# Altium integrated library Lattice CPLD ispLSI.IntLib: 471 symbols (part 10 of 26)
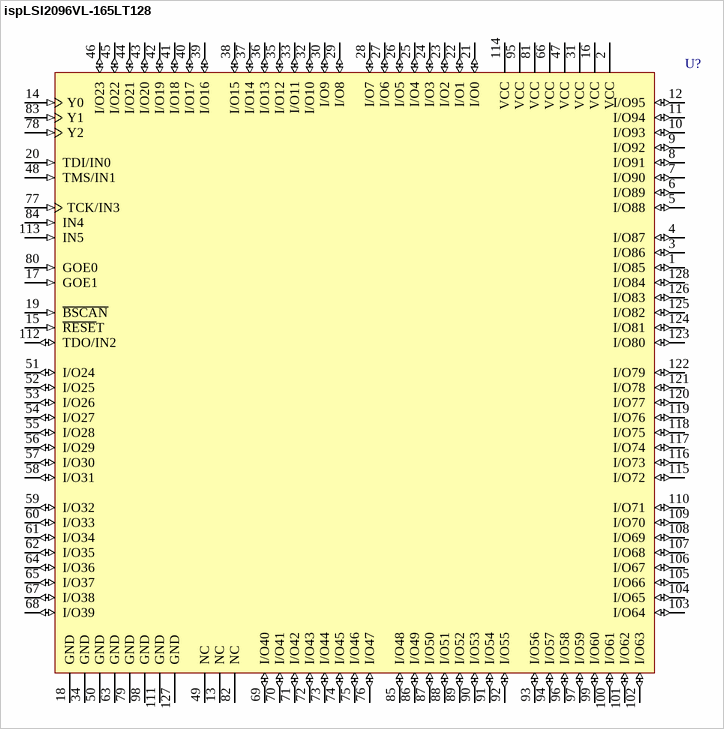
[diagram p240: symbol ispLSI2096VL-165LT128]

## ispLSI2096VL-165LT128
designator U?
2.5V In-System Programmable SuperFAST High Density PLD
footprint TQFP128_N (Thin QFP, 128-Leads, Body 14x14mm, Pitch 0.4mm, IPC Medium Density)
footprint TQFP128_L (Thin QFP, 128-Leads, Body 14x14mm, Pitch 0.4mm, IPC High Density)
footprint TQFP128_M (Thin QFP, 128-Leads, Body 14x14mm, Pitch 0.4mm, IPC Low Density)
3D model 2096VL-TQFP128 (128-Pin Thin Quad Flat Pack 0.4 mm Pitch)
pins: 1 I/O85 (io), 2 VCC (power), 3 I/O86 (io), 4 I/O87 (io), 5 I/O88 (io), 6 I/O89 (io), 7 I/O90 (io), 8 I/O91 (io), 9 I/O92 (io), 10 I/O93 (io), 11 I/O94 (io), 12 I/O95 (io), 13 NC, 14 Y0 (in), 15 ~{RESE}T (in), 16 VCC (power), 17 GOE1 (in), 18 GND (power), 19 ~{BSCAN} (in), 20 TDI/IN0 (in), 21 I/O0 (io), 22 I/O1 (io), 23 I/O2 (io), 24 I/O3 (io), 25 I/O4 (io), 26 I/O5 (io), 27 I/O6 (io), 28 I/O7 (io), 29 I/O8 (io), 30 I/O9 (io), 31 VCC (power), 32 I/O10 (io), 33 I/O11 (io), 34 GND (power), 35 I/O12 (io), 36 I/O13 (io), 37 I/O14 (io), 38 I/O15 (io), 39 I/O16 (io), 40 I/O17 (io), 41 I/O18 (io), 42 I/O19 (io), 43 I/O20 (io), 44 I/O21 (io), 45 I/O22 (io), 46 I/O23 (io), 47 VCC (power), 48 TMS/IN1 (in), 49 NC, 50 GND (power), 51 I/O24 (io), 52 I/O25 (io), 53 I/O26 (io), 54 I/O27 (io), 55 I/O28 (io), 56 I/O29 (io), 57 I/O30 (io), 58 I/O31 (io), 59 I/O32 (io), 60 I/O33 (io), 61 I/O34 (io), 62 I/O35 (io), 63 GND (power), 64 I/O36 (io), 65 I/O37 (io), 66 VCC (power), 67 I/O38 (io), 68 I/O39 (io), 69 I/O40 (io), 70 I/O41 (io), 71 I/O42 (io), 72 I/O43 (io), 73 I/O44 (io), 74 I/O45 (io), 75 I/O46 (io), 76 I/O47 (io), 77 TCK/IN3 (in), 78 Y2 (in), 79 GND (power), 80 GOE0 (in), 81 VCC (power), 82 NC, 83 Y1 (in), 84 IN4 (in), 85 I/O48 (io), 86 I/O49 (io), 87 I/O50 (io), 88 I/O51 (io), 89 I/O52 (io), 90 I/O53 (io), 91 I/O54 (io), 92 I/O55 (io), 93 I/O56 (io), 94 I/O57 (io), 95 VCC (power), 96 I/O58 (io), 97 I/O59 (io), 98 GND (power), 99 I/O60 (io), 100 I/O61 (io), 101 I/O62 (io), 102 I/O63 (io), 103 I/O64 (io), 104 I/O65 (io), 105 I/O66 (io), 106 I/O67 (io), 107 I/O68 (io), 108 I/O69 (io), 109 I/O70 (io), 110 I/O71 (io), 111 GND (power), 112 TDO/IN2 (io), 113 IN5 (in), 114 VCC (power), 115 I/O72 (io), 116 I/O73 (io), 117 I/O74 (io), 118 I/O75 (io), 119 I/O76 (io), 120 I/O77 (io), 121 I/O78 (io), 122 I/O79 (io), 123 I/O80 (io), 124 I/O81 (io), 125 I/O82 (io), 126 I/O83 (io), 127 GND (power), 128 I/O84 (io)

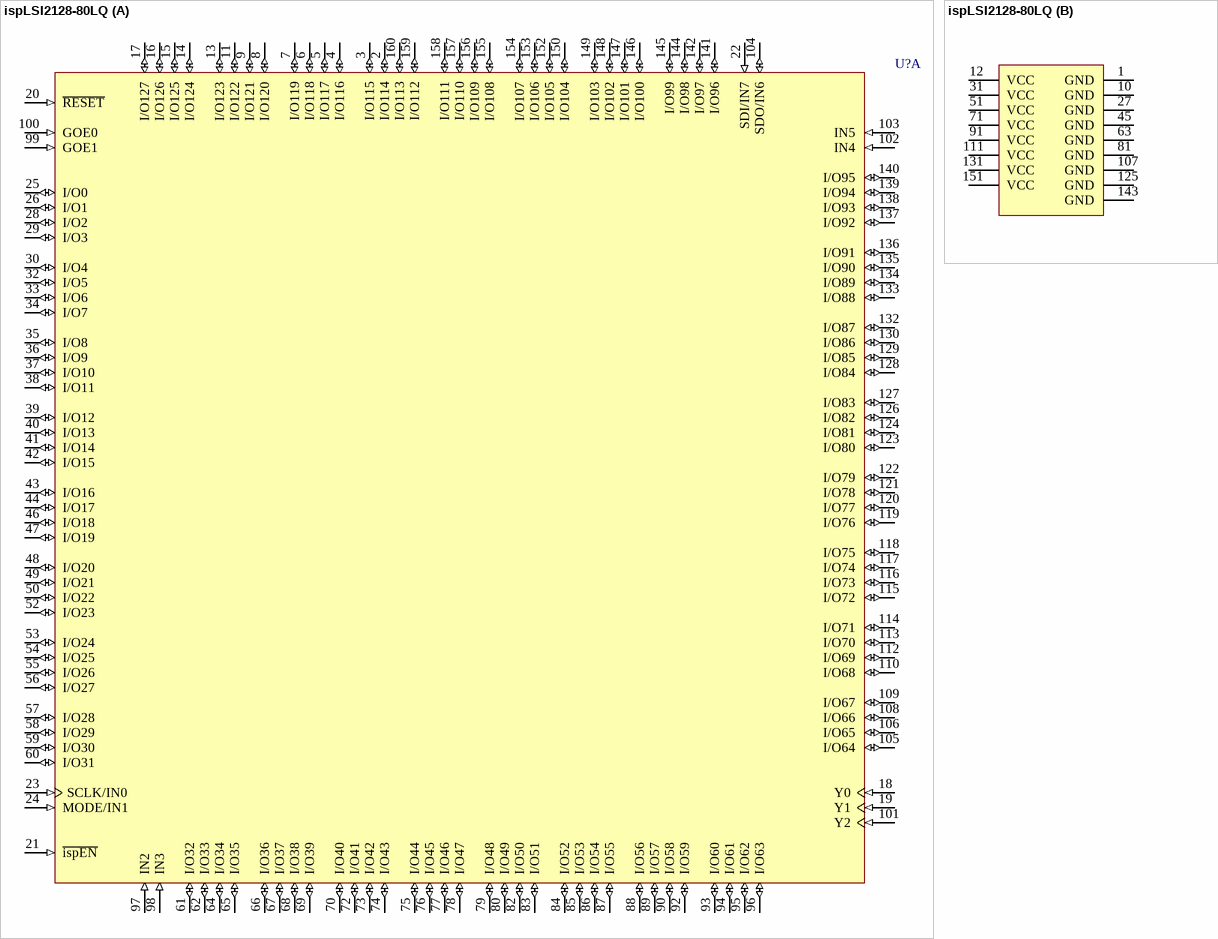
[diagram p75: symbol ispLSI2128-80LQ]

## ispLSI2128-80LQ
designator U?
In-System Programmable High-Density PLD; Note: Pins 22, 23, 24 and 104 have dual function capability.
footprint PQFP160_N (QFP, 160-Leads, Body 28 x 28mm, Pitch 0.65mm, IPC Medium Density)
footprint PQFP160_L (QFP, 160-Leads, Body 28 x 28mm, Pitch 0.65mm, IPC High Density)
footprint PQFP160_M (QFP, 160-Leads, Body 28 x 28mm, Pitch 0.65mm, IPC Low Density)
3D model 2128-PQFP160 (160-Pin Quad Flat Pack 0.65 mm Pitch)
part A pins: 2 I/O114 (io), 3 I/O115 (io), 4 I/O116 (io), 5 I/O117 (io), 6 I/O118 (io), 7 I/O119 (io), 8 I/O120 (io), 9 I/O121 (io), 11 I/O122 (io), 13 I/O123 (io), 14 I/O124 (io), 15 I/O125 (io), 16 I/O126 (io), 17 I/O127 (io), 18 Y0 (in), 19 Y1 (in), 20 ~{RESET} (in), 21 ~{ispEN} (in), 22 SDI/IN7 (in), 23 SCLK/IN0 (in), 24 MODE/IN1 (in), 25 I/O0 (io), 26 I/O1 (io), 28 I/O2 (io), 29 I/O3 (io), 30 I/O4 (io), 32 I/O5 (io), 33 I/O6 (io), 34 I/O7 (io), 35 I/O8 (io), 36 I/O9 (io), 37 I/O10 (io), 38 I/O11 (io), 39 I/O12 (io), 40 I/O13 (io), 41 I/O14 (io), 42 I/O15 (io), 43 I/O16 (io), 44 I/O17 (io), 46 I/O18 (io), 47 I/O19 (io), 48 I/O20 (io), 49 I/O21 (io), 50 I/O22 (io), 52 I/O23 (io), 53 I/O24 (io), 54 I/O25 (io), 55 I/O26 (io), 56 I/O27 (io), 57 I/O28 (io), 58 I/O29 (io), 59 I/O30 (io), 60 I/O31 (io), 61 I/O32 (io), 62 I/O33 (io), 64 I/O34 (io), 65 I/O35 (io), 66 I/O36 (io), 67 I/O37 (io), 68 I/O38 (io), 69 I/O39 (io), 70 I/O40 (io), 72 I/O41 (io), 73 I/O42 (io), 74 I/O43 (io), 75 I/O44 (io), 76 I/O45 (io), 77 I/O46 (io), 78 I/O47 (io), 79 I/O48 (io), 80 I/O49 (io), 82 I/O50 (io), 83 I/O51 (io), 84 I/O52 (io), 85 I/O53 (io), 86 I/O54 (io), 87 I/O55 (io), 88 I/O56 (io), 89 I/O57 (io), 90 I/O58 (io), 92 I/O59 (io), 93 I/O60 (io), 94 I/O61 (io), 95 I/O62 (io), 96 I/O63 (io), 97 IN2 (in), 98 IN3 (in), 99 GOE1 (in), 100 GOE0 (in), 101 Y2 (in), 102 IN4 (in), 103 IN5 (in), 104 SDO/IN6 (io), 105 I/O64 (io), 106 I/O65 (io), 108 I/O66 (io), 109 I/O67 (io), 110 I/O68 (io), 112 I/O69 (io), 113 I/O70 (io), 114 I/O71 (io), 115 I/O72 (io), 116 I/O73 (io), 117 I/O74 (io), 118 I/O75 (io), 119 I/O76 (io), 120 I/O77 (io), 121 I/O78 (io), 122 I/O79 (io), 123 I/O80 (io), 124 I/O81 (io), 126 I/O82 (io), 127 I/O83 (io), 128 I/O84 (io), 129 I/O85 (io), 130 I/O86 (io), 132 I/O87 (io), 133 I/O88 (io), 134 I/O89 (io), 135 I/O90 (io), 136 I/O91 (io), 137 I/O92 (io), 138 I/O93 (io), 139 I/O94 (io), 140 I/O95 (io), 141 I/O96 (io), 142 I/O97 (io), 144 I/O98 (io), 145 I/O99 (io), 146 I/O100 (io), 147 I/O101 (io), 148 I/O102 (io), 149 I/O103 (io), 150 I/O104 (io), 152 I/O105 (io), 153 I/O106 (io), 154 I/O107 (io), 155 I/O108 (io), 156 I/O109 (io), 157 I/O110 (io), 158 I/O111 (io), 159 I/O112 (io), 160 I/O113 (io)
part B pins: 1 GND (power), 10 GND (power), 12 VCC (power), 27 GND (power), 31 VCC (power), 45 GND (power), 51 VCC (power), 63 GND (power), 71 VCC (power), 81 GND (power), 91 VCC (power), 107 GND (power), 111 VCC (power), 125 GND (power), 131 VCC (power), 143 GND (power), 151 VCC (power)

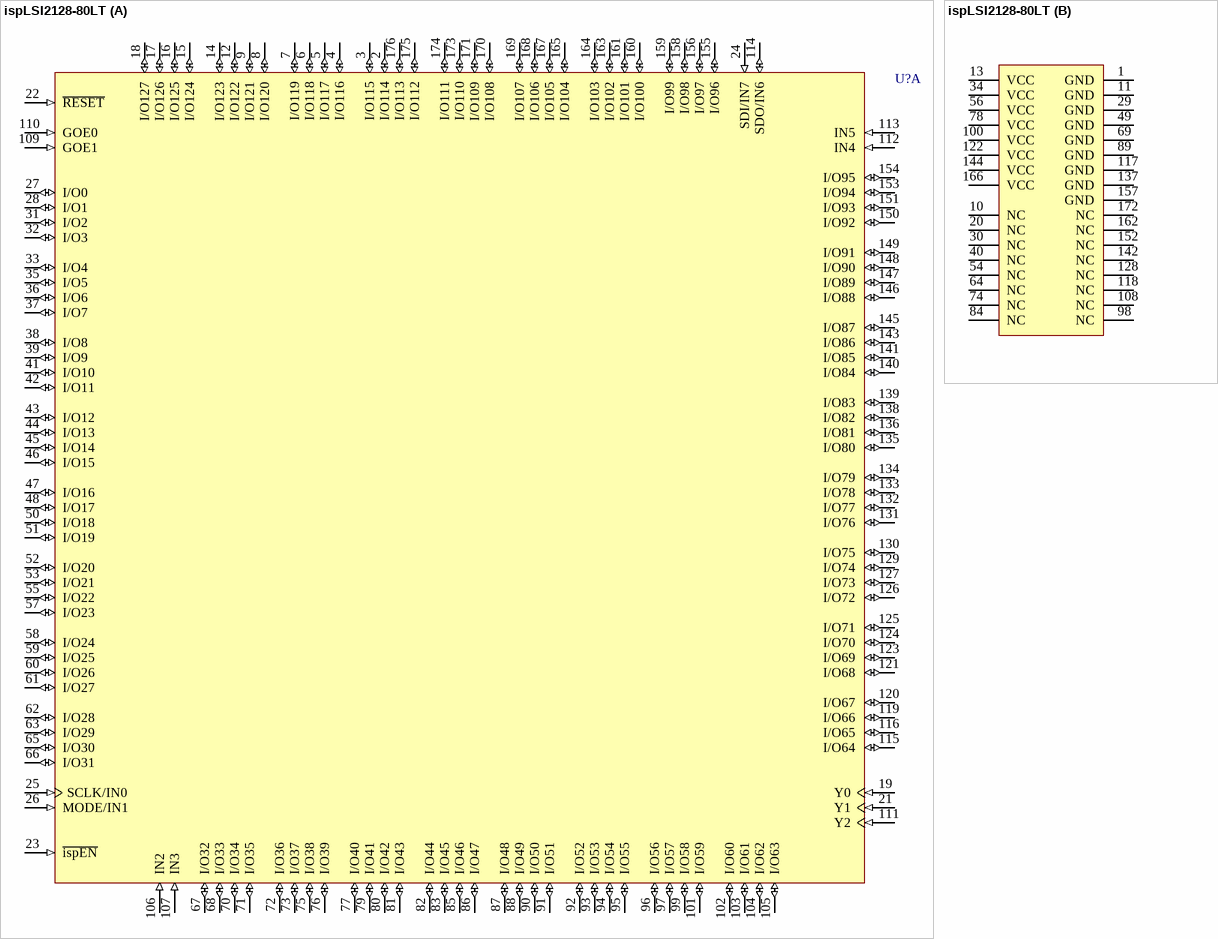
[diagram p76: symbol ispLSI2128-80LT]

## ispLSI2128-80LT
designator U?
In-System Programmable High-Density PLD; Note: Pins 24, 25, 26 and 114 have dual function capability.
footprint TQFP176_N (Thin QFP, 176-Leads, Body 24x24mm, Pitch 0.5mm, IPC Medium Density)
footprint TQFP176_L (Thin QFP, 176-Leads, Body 24x24mm, Pitch 0.5mm, IPC High Density)
footprint TQFP176_M (Thin QFP, 176-Leads, Body 24x24mm, Pitch 0.5mm, IPC Low Density)
3D model 2128-TQFP176 (176-Pin Thin Quad Flat Pack 0.5 mm Pitch)
part A pins: 2 I/O114 (io), 3 I/O115 (io), 4 I/O116 (io), 5 I/O117 (io), 6 I/O118 (io), 7 I/O119 (io), 8 I/O120 (io), 9 I/O121 (io), 12 I/O122 (io), 14 I/O123 (io), 15 I/O124 (io), 16 I/O125 (io), 17 I/O126 (io), 18 I/O127 (io), 19 Y0 (in), 21 Y1 (in), 22 ~{RESET} (in), 23 ~{ispEN} (in), 24 SDI/IN7 (in), 25 SCLK/IN0 (in), 26 MODE/IN1 (in), 27 I/O0 (io), 28 I/O1 (io), 31 I/O2 (io), 32 I/O3 (io), 33 I/O4 (io), 35 I/O5 (io), 36 I/O6 (io), 37 I/O7 (io), 38 I/O8 (io), 39 I/O9 (io), 41 I/O10 (io), 42 I/O11 (io), 43 I/O12 (io), 44 I/O13 (io), 45 I/O14 (io), 46 I/O15 (io), 47 I/O16 (io), 48 I/O17 (io), 50 I/O18 (io), 51 I/O19 (io), 52 I/O20 (io), 53 I/O21 (io), 55 I/O22 (io), 57 I/O23 (io), 58 I/O24 (io), 59 I/O25 (io), 60 I/O26 (io), 61 I/O27 (io), 62 I/O28 (io), 63 I/O29 (io), 65 I/O30 (io), 66 I/O31 (io), 67 I/O32 (io), 68 I/O33 (io), 70 I/O34 (io), 71 I/O35 (io), 72 I/O36 (io), 73 I/O37 (io), 75 I/O38 (io), 76 I/O39 (io), 77 I/O40 (io), 79 I/O41 (io), 80 I/O42 (io), 81 I/O43 (io), 82 I/O44 (io), 83 I/O45 (io), 85 I/O46 (io), 86 I/O47 (io), 87 I/O48 (io), 88 I/O49 (io), 90 I/O50 (io), 91 I/O51 (io), 92 I/O52 (io), 93 I/O53 (io), 94 I/O54 (io), 95 I/O55 (io), 96 I/O56 (io), 97 I/O57 (io), 99 I/O58 (io), 101 I/O59 (io), 102 I/O60 (io), 103 I/O61 (io), 104 I/O62 (io), 105 I/O63 (io), 106 IN2 (in), 107 IN3 (in), 109 GOE1 (in), 110 GOE0 (in), 111 Y2 (in), 112 IN4 (in), 113 IN5 (in), 114 SDO/IN6 (io), 115 I/O64 (io), 116 I/O65 (io), 119 I/O66 (io), 120 I/O67 (io), 121 I/O68 (io), 123 I/O69 (io), 124 I/O70 (io), 125 I/O71 (io), 126 I/O72 (io), 127 I/O73 (io), 129 I/O74 (io), 130 I/O75 (io), 131 I/O76 (io), 132 I/O77 (io), 133 I/O78 (io), 134 I/O79 (io), 135 I/O80 (io), 136 I/O81 (io), 138 I/O82 (io), 139 I/O83 (io), 140 I/O84 (io), 141 I/O85 (io), 143 I/O86 (io), 145 I/O87 (io), 146 I/O88 (io), 147 I/O89 (io), 148 I/O90 (io), 149 I/O91 (io), 150 I/O92 (io), 151 I/O93 (io), 153 I/O94 (io), 154 I/O95 (io), 155 I/O96 (io), 156 I/O97 (io), 158 I/O98 (io), 159 I/O99 (io), 160 I/O100 (io), 161 I/O101 (io), 163 I/O102 (io), 164 I/O103 (io), 165 I/O104 (io), 167 I/O105 (io), 168 I/O106 (io), 169 I/O107 (io), 170 I/O108 (io), 171 I/O109 (io), 173 I/O110 (io), 174 I/O111 (io), 175 I/O112 (io), 176 I/O113 (io)
part B pins: 1 GND (power), 10 NC, 11 GND (power), 13 VCC (power), 20 NC, 29 GND (power), 30 NC, 34 VCC (power), 40 NC, 49 GND (power), 54 NC, 56 VCC (power), 64 NC, 69 GND (power), 74 NC, 78 VCC (power), 84 NC, 89 GND (power), 98 NC, 100 VCC (power), 108 NC, 117 GND (power), 118 NC, 122 VCC (power), 128 NC, 137 GND (power), 142 NC, 144 VCC (power), 152 NC, 157 GND (power), 162 NC, 166 VCC (power), 172 NC

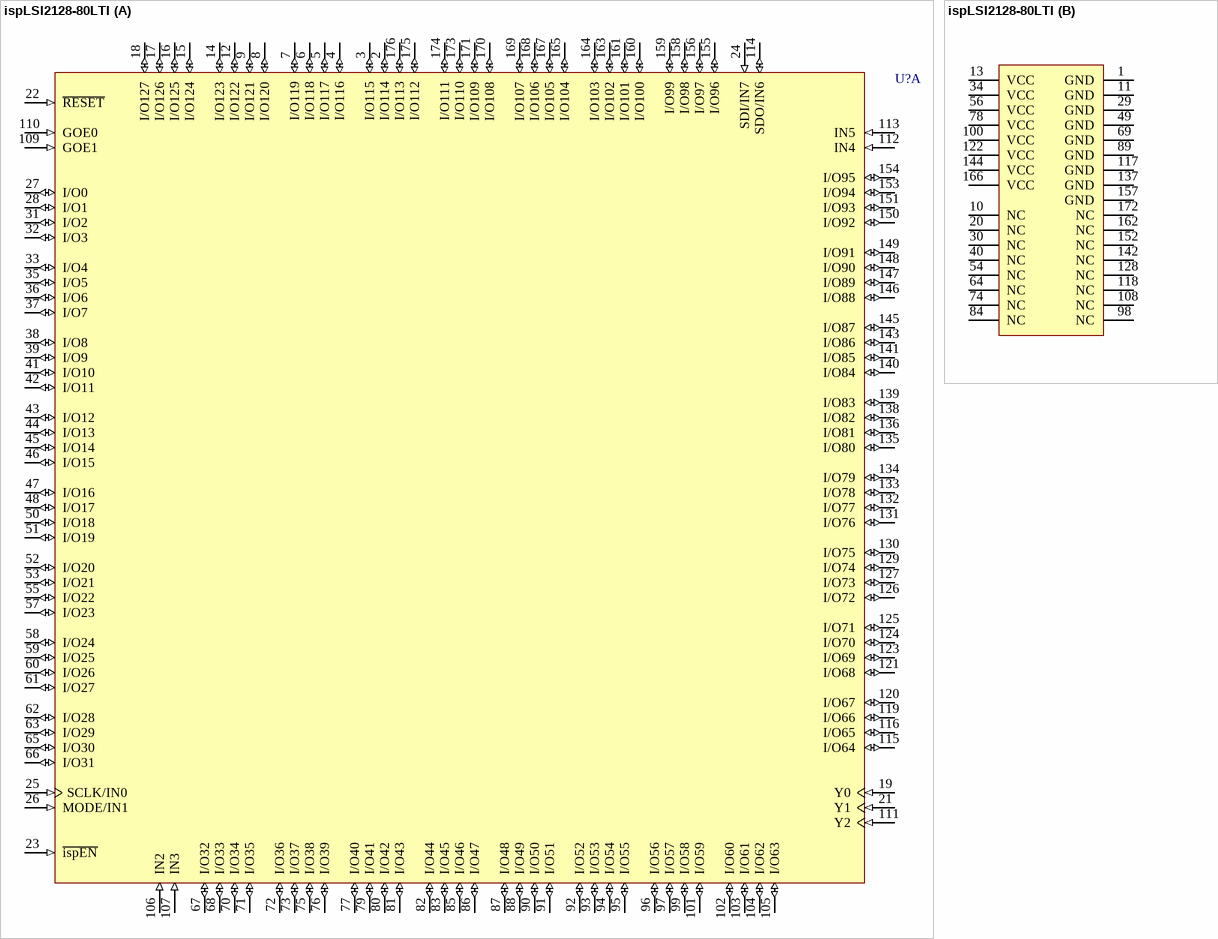
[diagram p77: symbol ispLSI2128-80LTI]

## ispLSI2128-80LTI
designator U?
In-System Programmable High-Density PLD; Note: Pins 24, 25, 26 and 114 have dual function capability.
footprint TQFP176_N (Thin QFP, 176-Leads, Body 24x24mm, Pitch 0.5mm, IPC Medium Density)
footprint TQFP176_L (Thin QFP, 176-Leads, Body 24x24mm, Pitch 0.5mm, IPC High Density)
footprint TQFP176_M (Thin QFP, 176-Leads, Body 24x24mm, Pitch 0.5mm, IPC Low Density)
3D model 2128-TQFP176 (176-Pin Thin Quad Flat Pack 0.5 mm Pitch)
part A pins: 2 I/O114 (io), 3 I/O115 (io), 4 I/O116 (io), 5 I/O117 (io), 6 I/O118 (io), 7 I/O119 (io), 8 I/O120 (io), 9 I/O121 (io), 12 I/O122 (io), 14 I/O123 (io), 15 I/O124 (io), 16 I/O125 (io), 17 I/O126 (io), 18 I/O127 (io), 19 Y0 (in), 21 Y1 (in), 22 ~{RESET} (in), 23 ~{ispEN} (in), 24 SDI/IN7 (in), 25 SCLK/IN0 (in), 26 MODE/IN1 (in), 27 I/O0 (io), 28 I/O1 (io), 31 I/O2 (io), 32 I/O3 (io), 33 I/O4 (io), 35 I/O5 (io), 36 I/O6 (io), 37 I/O7 (io), 38 I/O8 (io), 39 I/O9 (io), 41 I/O10 (io), 42 I/O11 (io), 43 I/O12 (io), 44 I/O13 (io), 45 I/O14 (io), 46 I/O15 (io), 47 I/O16 (io), 48 I/O17 (io), 50 I/O18 (io), 51 I/O19 (io), 52 I/O20 (io), 53 I/O21 (io), 55 I/O22 (io), 57 I/O23 (io), 58 I/O24 (io), 59 I/O25 (io), 60 I/O26 (io), 61 I/O27 (io), 62 I/O28 (io), 63 I/O29 (io), 65 I/O30 (io), 66 I/O31 (io), 67 I/O32 (io), 68 I/O33 (io), 70 I/O34 (io), 71 I/O35 (io), 72 I/O36 (io), 73 I/O37 (io), 75 I/O38 (io), 76 I/O39 (io), 77 I/O40 (io), 79 I/O41 (io), 80 I/O42 (io), 81 I/O43 (io), 82 I/O44 (io), 83 I/O45 (io), 85 I/O46 (io), 86 I/O47 (io), 87 I/O48 (io), 88 I/O49 (io), 90 I/O50 (io), 91 I/O51 (io), 92 I/O52 (io), 93 I/O53 (io), 94 I/O54 (io), 95 I/O55 (io), 96 I/O56 (io), 97 I/O57 (io), 99 I/O58 (io), 101 I/O59 (io), 102 I/O60 (io), 103 I/O61 (io), 104 I/O62 (io), 105 I/O63 (io), 106 IN2 (in), 107 IN3 (in), 109 GOE1 (in), 110 GOE0 (in), 111 Y2 (in), 112 IN4 (in), 113 IN5 (in), 114 SDO/IN6 (io), 115 I/O64 (io), 116 I/O65 (io), 119 I/O66 (io), 120 I/O67 (io), 121 I/O68 (io), 123 I/O69 (io), 124 I/O70 (io), 125 I/O71 (io), 126 I/O72 (io), 127 I/O73 (io), 129 I/O74 (io), 130 I/O75 (io), 131 I/O76 (io), 132 I/O77 (io), 133 I/O78 (io), 134 I/O79 (io), 135 I/O80 (io), 136 I/O81 (io), 138 I/O82 (io), 139 I/O83 (io), 140 I/O84 (io), 141 I/O85 (io), 143 I/O86 (io), 145 I/O87 (io), 146 I/O88 (io), 147 I/O89 (io), 148 I/O90 (io), 149 I/O91 (io), 150 I/O92 (io), 151 I/O93 (io), 153 I/O94 (io), 154 I/O95 (io), 155 I/O96 (io), 156 I/O97 (io), 158 I/O98 (io), 159 I/O99 (io), 160 I/O100 (io), 161 I/O101 (io), 163 I/O102 (io), 164 I/O103 (io), 165 I/O104 (io), 167 I/O105 (io), 168 I/O106 (io), 169 I/O107 (io), 170 I/O108 (io), 171 I/O109 (io), 173 I/O110 (io), 174 I/O111 (io), 175 I/O112 (io), 176 I/O113 (io)
part B pins: 1 GND (power), 10 NC, 11 GND (power), 13 VCC (power), 20 NC, 29 GND (power), 30 NC, 34 VCC (power), 40 NC, 49 GND (power), 54 NC, 56 VCC (power), 64 NC, 69 GND (power), 74 NC, 78 VCC (power), 84 NC, 89 GND (power), 98 NC, 100 VCC (power), 108 NC, 117 GND (power), 118 NC, 122 VCC (power), 128 NC, 137 GND (power), 142 NC, 144 VCC (power), 152 NC, 157 GND (power), 162 NC, 166 VCC (power), 172 NC

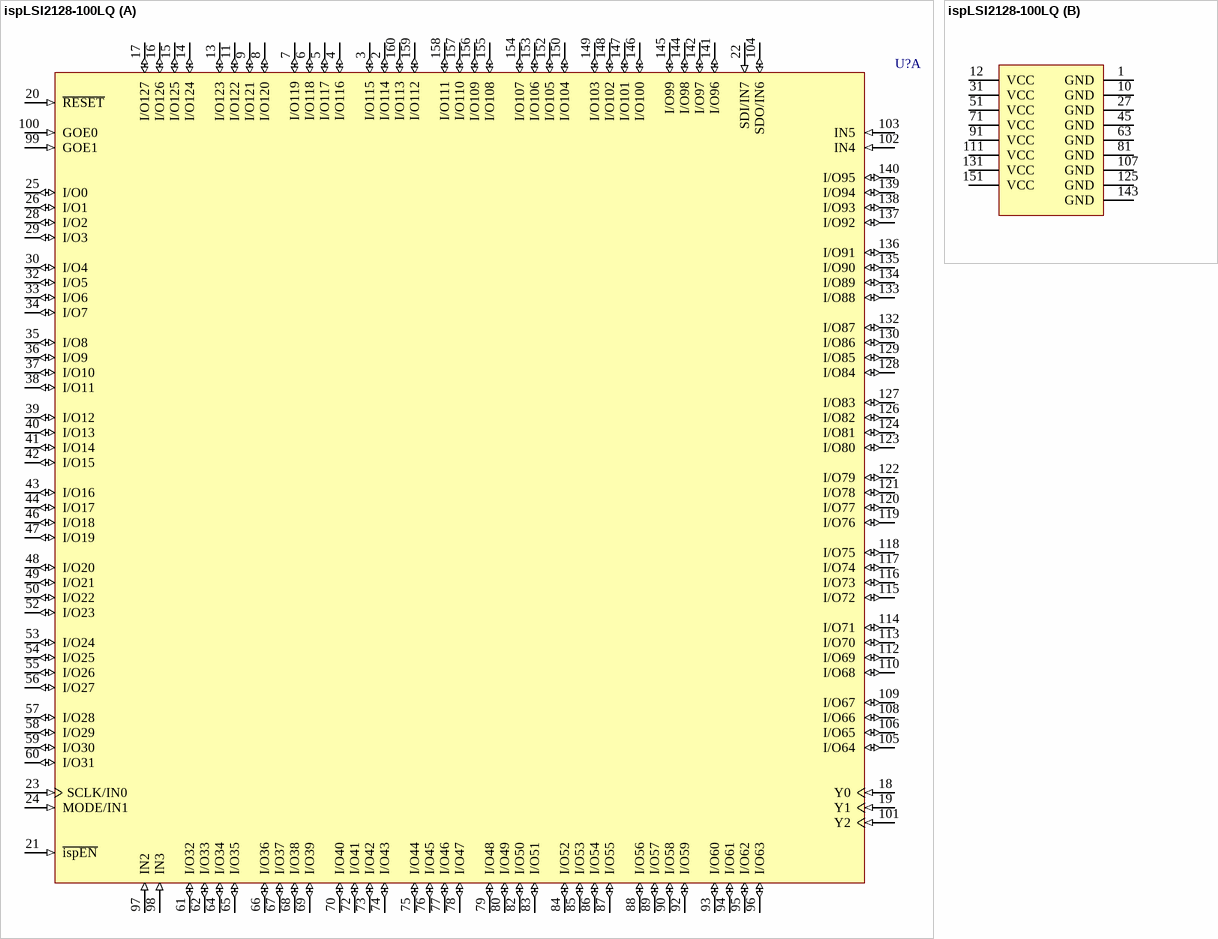
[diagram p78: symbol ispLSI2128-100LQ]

## ispLSI2128-100LQ
designator U?
In-System Programmable High-Density PLD; Note: Pins 22, 23, 24 and 104 have dual function capability.
footprint PQFP160_N (QFP, 160-Leads, Body 28 x 28mm, Pitch 0.65mm, IPC Medium Density)
footprint PQFP160_L (QFP, 160-Leads, Body 28 x 28mm, Pitch 0.65mm, IPC High Density)
footprint PQFP160_M (QFP, 160-Leads, Body 28 x 28mm, Pitch 0.65mm, IPC Low Density)
3D model 2128-PQFP160 (160-Pin Quad Flat Pack 0.65 mm Pitch)
part A pins: 2 I/O114 (io), 3 I/O115 (io), 4 I/O116 (io), 5 I/O117 (io), 6 I/O118 (io), 7 I/O119 (io), 8 I/O120 (io), 9 I/O121 (io), 11 I/O122 (io), 13 I/O123 (io), 14 I/O124 (io), 15 I/O125 (io), 16 I/O126 (io), 17 I/O127 (io), 18 Y0 (in), 19 Y1 (in), 20 ~{RESET} (in), 21 ~{ispEN} (in), 22 SDI/IN7 (in), 23 SCLK/IN0 (in), 24 MODE/IN1 (in), 25 I/O0 (io), 26 I/O1 (io), 28 I/O2 (io), 29 I/O3 (io), 30 I/O4 (io), 32 I/O5 (io), 33 I/O6 (io), 34 I/O7 (io), 35 I/O8 (io), 36 I/O9 (io), 37 I/O10 (io), 38 I/O11 (io), 39 I/O12 (io), 40 I/O13 (io), 41 I/O14 (io), 42 I/O15 (io), 43 I/O16 (io), 44 I/O17 (io), 46 I/O18 (io), 47 I/O19 (io), 48 I/O20 (io), 49 I/O21 (io), 50 I/O22 (io), 52 I/O23 (io), 53 I/O24 (io), 54 I/O25 (io), 55 I/O26 (io), 56 I/O27 (io), 57 I/O28 (io), 58 I/O29 (io), 59 I/O30 (io), 60 I/O31 (io), 61 I/O32 (io), 62 I/O33 (io), 64 I/O34 (io), 65 I/O35 (io), 66 I/O36 (io), 67 I/O37 (io), 68 I/O38 (io), 69 I/O39 (io), 70 I/O40 (io), 72 I/O41 (io), 73 I/O42 (io), 74 I/O43 (io), 75 I/O44 (io), 76 I/O45 (io), 77 I/O46 (io), 78 I/O47 (io), 79 I/O48 (io), 80 I/O49 (io), 82 I/O50 (io), 83 I/O51 (io), 84 I/O52 (io), 85 I/O53 (io), 86 I/O54 (io), 87 I/O55 (io), 88 I/O56 (io), 89 I/O57 (io), 90 I/O58 (io), 92 I/O59 (io), 93 I/O60 (io), 94 I/O61 (io), 95 I/O62 (io), 96 I/O63 (io), 97 IN2 (in), 98 IN3 (in), 99 GOE1 (in), 100 GOE0 (in), 101 Y2 (in), 102 IN4 (in), 103 IN5 (in), 104 SDO/IN6 (io), 105 I/O64 (io), 106 I/O65 (io), 108 I/O66 (io), 109 I/O67 (io), 110 I/O68 (io), 112 I/O69 (io), 113 I/O70 (io), 114 I/O71 (io), 115 I/O72 (io), 116 I/O73 (io), 117 I/O74 (io), 118 I/O75 (io), 119 I/O76 (io), 120 I/O77 (io), 121 I/O78 (io), 122 I/O79 (io), 123 I/O80 (io), 124 I/O81 (io), 126 I/O82 (io), 127 I/O83 (io), 128 I/O84 (io), 129 I/O85 (io), 130 I/O86 (io), 132 I/O87 (io), 133 I/O88 (io), 134 I/O89 (io), 135 I/O90 (io), 136 I/O91 (io), 137 I/O92 (io), 138 I/O93 (io), 139 I/O94 (io), 140 I/O95 (io), 141 I/O96 (io), 142 I/O97 (io), 144 I/O98 (io), 145 I/O99 (io), 146 I/O100 (io), 147 I/O101 (io), 148 I/O102 (io), 149 I/O103 (io), 150 I/O104 (io), 152 I/O105 (io), 153 I/O106 (io), 154 I/O107 (io), 155 I/O108 (io), 156 I/O109 (io), 157 I/O110 (io), 158 I/O111 (io), 159 I/O112 (io), 160 I/O113 (io)
part B pins: 1 GND (power), 10 GND (power), 12 VCC (power), 27 GND (power), 31 VCC (power), 45 GND (power), 51 VCC (power), 63 GND (power), 71 VCC (power), 81 GND (power), 91 VCC (power), 107 GND (power), 111 VCC (power), 125 GND (power), 131 VCC (power), 143 GND (power), 151 VCC (power)

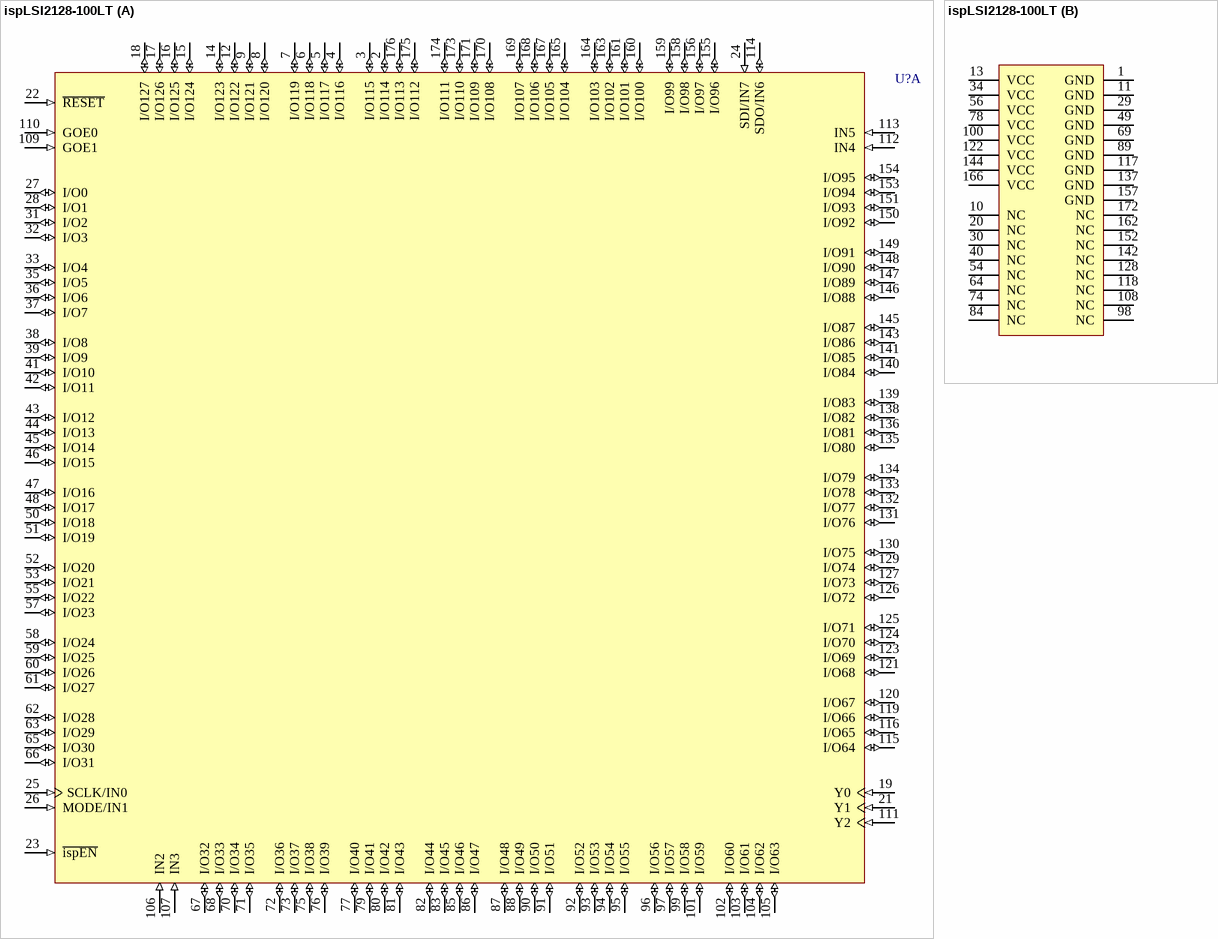
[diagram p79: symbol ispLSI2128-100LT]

## ispLSI2128-100LT
designator U?
In-System Programmable High-Density PLD; Note: Pins 24, 25, 26 and 114 have dual function capability.
footprint TQFP176_N (Thin QFP, 176-Leads, Body 24x24mm, Pitch 0.5mm, IPC Medium Density)
footprint TQFP176_L (Thin QFP, 176-Leads, Body 24x24mm, Pitch 0.5mm, IPC High Density)
footprint TQFP176_M (Thin QFP, 176-Leads, Body 24x24mm, Pitch 0.5mm, IPC Low Density)
3D model 2128-TQFP176 (176-Pin Thin Quad Flat Pack 0.5 mm Pitch)
part A pins: 2 I/O114 (io), 3 I/O115 (io), 4 I/O116 (io), 5 I/O117 (io), 6 I/O118 (io), 7 I/O119 (io), 8 I/O120 (io), 9 I/O121 (io), 12 I/O122 (io), 14 I/O123 (io), 15 I/O124 (io), 16 I/O125 (io), 17 I/O126 (io), 18 I/O127 (io), 19 Y0 (in), 21 Y1 (in), 22 ~{RESET} (in), 23 ~{ispEN} (in), 24 SDI/IN7 (in), 25 SCLK/IN0 (in), 26 MODE/IN1 (in), 27 I/O0 (io), 28 I/O1 (io), 31 I/O2 (io), 32 I/O3 (io), 33 I/O4 (io), 35 I/O5 (io), 36 I/O6 (io), 37 I/O7 (io), 38 I/O8 (io), 39 I/O9 (io), 41 I/O10 (io), 42 I/O11 (io), 43 I/O12 (io), 44 I/O13 (io), 45 I/O14 (io), 46 I/O15 (io), 47 I/O16 (io), 48 I/O17 (io), 50 I/O18 (io), 51 I/O19 (io), 52 I/O20 (io), 53 I/O21 (io), 55 I/O22 (io), 57 I/O23 (io), 58 I/O24 (io), 59 I/O25 (io), 60 I/O26 (io), 61 I/O27 (io), 62 I/O28 (io), 63 I/O29 (io), 65 I/O30 (io), 66 I/O31 (io), 67 I/O32 (io), 68 I/O33 (io), 70 I/O34 (io), 71 I/O35 (io), 72 I/O36 (io), 73 I/O37 (io), 75 I/O38 (io), 76 I/O39 (io), 77 I/O40 (io), 79 I/O41 (io), 80 I/O42 (io), 81 I/O43 (io), 82 I/O44 (io), 83 I/O45 (io), 85 I/O46 (io), 86 I/O47 (io), 87 I/O48 (io), 88 I/O49 (io), 90 I/O50 (io), 91 I/O51 (io), 92 I/O52 (io), 93 I/O53 (io), 94 I/O54 (io), 95 I/O55 (io), 96 I/O56 (io), 97 I/O57 (io), 99 I/O58 (io), 101 I/O59 (io), 102 I/O60 (io), 103 I/O61 (io), 104 I/O62 (io), 105 I/O63 (io), 106 IN2 (in), 107 IN3 (in), 109 GOE1 (in), 110 GOE0 (in), 111 Y2 (in), 112 IN4 (in), 113 IN5 (in), 114 SDO/IN6 (io), 115 I/O64 (io), 116 I/O65 (io), 119 I/O66 (io), 120 I/O67 (io), 121 I/O68 (io), 123 I/O69 (io), 124 I/O70 (io), 125 I/O71 (io), 126 I/O72 (io), 127 I/O73 (io), 129 I/O74 (io), 130 I/O75 (io), 131 I/O76 (io), 132 I/O77 (io), 133 I/O78 (io), 134 I/O79 (io), 135 I/O80 (io), 136 I/O81 (io), 138 I/O82 (io), 139 I/O83 (io), 140 I/O84 (io), 141 I/O85 (io), 143 I/O86 (io), 145 I/O87 (io), 146 I/O88 (io), 147 I/O89 (io), 148 I/O90 (io), 149 I/O91 (io), 150 I/O92 (io), 151 I/O93 (io), 153 I/O94 (io), 154 I/O95 (io), 155 I/O96 (io), 156 I/O97 (io), 158 I/O98 (io), 159 I/O99 (io), 160 I/O100 (io), 161 I/O101 (io), 163 I/O102 (io), 164 I/O103 (io), 165 I/O104 (io), 167 I/O105 (io), 168 I/O106 (io), 169 I/O107 (io), 170 I/O108 (io), 171 I/O109 (io), 173 I/O110 (io), 174 I/O111 (io), 175 I/O112 (io), 176 I/O113 (io)
part B pins: 1 GND (power), 10 NC, 11 GND (power), 13 VCC (power), 20 NC, 29 GND (power), 30 NC, 34 VCC (power), 40 NC, 49 GND (power), 54 NC, 56 VCC (power), 64 NC, 69 GND (power), 74 NC, 78 VCC (power), 84 NC, 89 GND (power), 98 NC, 100 VCC (power), 108 NC, 117 GND (power), 118 NC, 122 VCC (power), 128 NC, 137 GND (power), 142 NC, 144 VCC (power), 152 NC, 157 GND (power), 162 NC, 166 VCC (power), 172 NC

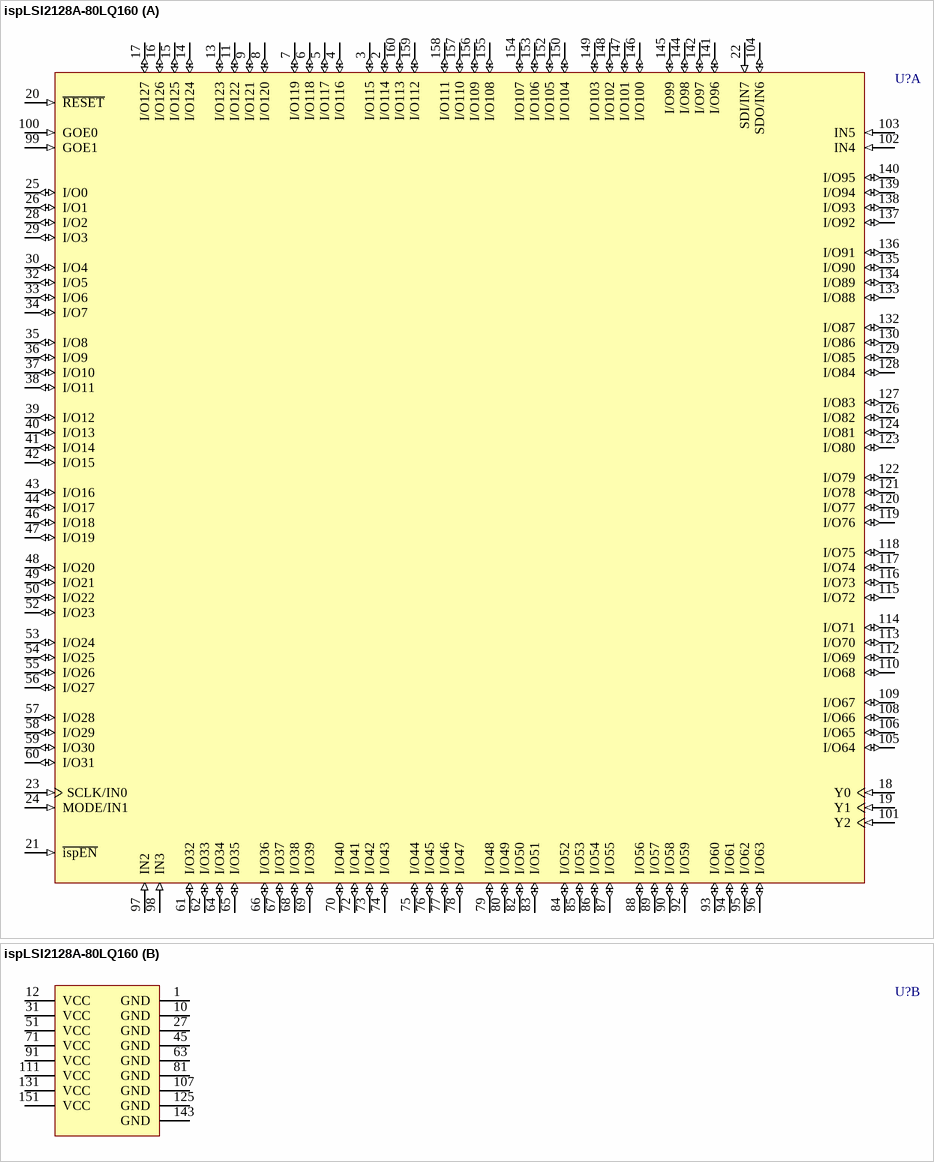
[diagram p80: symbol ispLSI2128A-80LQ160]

## ispLSI2128A-80LQ160
designator U?
In-System Programmable High-Density PLD; Note: Pins 22, 23, 24 and 104 have dual function capability.
footprint PQFP160_N (QFP, 160-Leads, Body 28 x 28mm, Pitch 0.65mm, IPC Medium Density)
footprint PQFP160_L (QFP, 160-Leads, Body 28 x 28mm, Pitch 0.65mm, IPC High Density)
footprint PQFP160_M (QFP, 160-Leads, Body 28 x 28mm, Pitch 0.65mm, IPC Low Density)
3D model 2128A-PQFP160 (160-Pin Quad Flat Pack 0.65 mm Pitch)
part A pins: 2 I/O114 (io), 3 I/O115 (io), 4 I/O116 (io), 5 I/O117 (io), 6 I/O118 (io), 7 I/O119 (io), 8 I/O120 (io), 9 I/O121 (io), 11 I/O122 (io), 13 I/O123 (io), 14 I/O124 (io), 15 I/O125 (io), 16 I/O126 (io), 17 I/O127 (io), 18 Y0 (in), 19 Y1 (in), 20 ~{RESET} (in), 21 ~{ispEN} (in), 22 SDI/IN7 (in), 23 SCLK/IN0 (in), 24 MODE/IN1 (in), 25 I/O0 (io), 26 I/O1 (io), 28 I/O2 (io), 29 I/O3 (io), 30 I/O4 (io), 32 I/O5 (io), 33 I/O6 (io), 34 I/O7 (io), 35 I/O8 (io), 36 I/O9 (io), 37 I/O10 (io), 38 I/O11 (io), 39 I/O12 (io), 40 I/O13 (io), 41 I/O14 (io), 42 I/O15 (io), 43 I/O16 (io), 44 I/O17 (io), 46 I/O18 (io), 47 I/O19 (io), 48 I/O20 (io), 49 I/O21 (io), 50 I/O22 (io), 52 I/O23 (io), 53 I/O24 (io), 54 I/O25 (io), 55 I/O26 (io), 56 I/O27 (io), 57 I/O28 (io), 58 I/O29 (io), 59 I/O30 (io), 60 I/O31 (io), 61 I/O32 (io), 62 I/O33 (io), 64 I/O34 (io), 65 I/O35 (io), 66 I/O36 (io), 67 I/O37 (io), 68 I/O38 (io), 69 I/O39 (io), 70 I/O40 (io), 72 I/O41 (io), 73 I/O42 (io), 74 I/O43 (io), 75 I/O44 (io), 76 I/O45 (io), 77 I/O46 (io), 78 I/O47 (io), 79 I/O48 (io), 80 I/O49 (io), 82 I/O50 (io), 83 I/O51 (io), 84 I/O52 (io), 85 I/O53 (io), 86 I/O54 (io), 87 I/O55 (io), 88 I/O56 (io), 89 I/O57 (io), 90 I/O58 (io), 92 I/O59 (io), 93 I/O60 (io), 94 I/O61 (io), 95 I/O62 (io), 96 I/O63 (io), 97 IN2 (in), 98 IN3 (in), 99 GOE1 (in), 100 GOE0 (in), 101 Y2 (in), 102 IN4 (in), 103 IN5 (in), 104 SDO/IN6 (io), 105 I/O64 (io), 106 I/O65 (io), 108 I/O66 (io), 109 I/O67 (io), 110 I/O68 (io), 112 I/O69 (io), 113 I/O70 (io), 114 I/O71 (io), 115 I/O72 (io), 116 I/O73 (io), 117 I/O74 (io), 118 I/O75 (io), 119 I/O76 (io), 120 I/O77 (io), 121 I/O78 (io), 122 I/O79 (io), 123 I/O80 (io), 124 I/O81 (io), 126 I/O82 (io), 127 I/O83 (io), 128 I/O84 (io), 129 I/O85 (io), 130 I/O86 (io), 132 I/O87 (io), 133 I/O88 (io), 134 I/O89 (io), 135 I/O90 (io), 136 I/O91 (io), 137 I/O92 (io), 138 I/O93 (io), 139 I/O94 (io), 140 I/O95 (io), 141 I/O96 (io), 142 I/O97 (io), 144 I/O98 (io), 145 I/O99 (io), 146 I/O100 (io), 147 I/O101 (io), 148 I/O102 (io), 149 I/O103 (io), 150 I/O104 (io), 152 I/O105 (io), 153 I/O106 (io), 154 I/O107 (io), 155 I/O108 (io), 156 I/O109 (io), 157 I/O110 (io), 158 I/O111 (io), 159 I/O112 (io), 160 I/O113 (io)
part B pins: 1 GND (power), 10 GND (power), 12 VCC (power), 27 GND (power), 31 VCC (power), 45 GND (power), 51 VCC (power), 63 GND (power), 71 VCC (power), 81 GND (power), 91 VCC (power), 107 GND (power), 111 VCC (power), 125 GND (power), 131 VCC (power), 143 GND (power), 151 VCC (power)

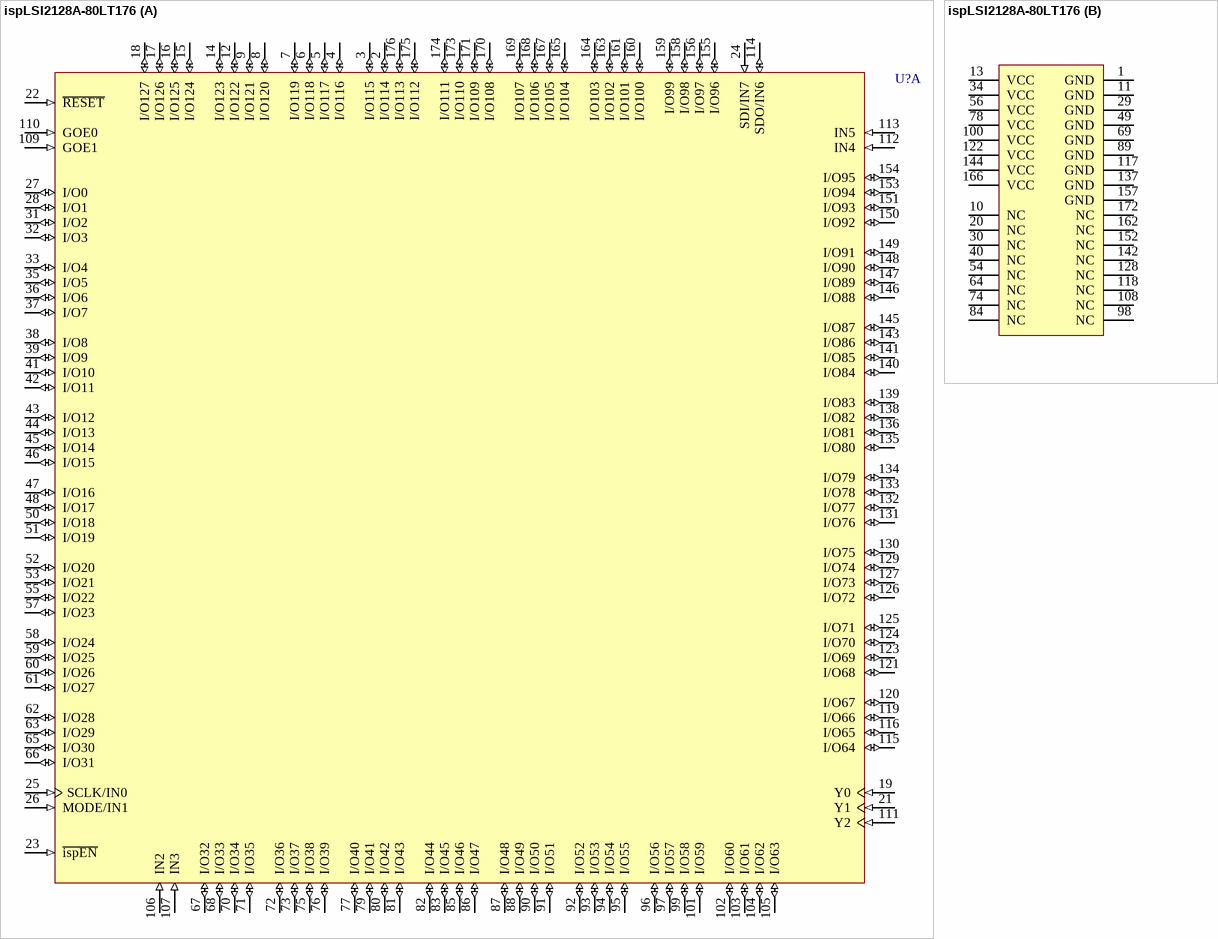
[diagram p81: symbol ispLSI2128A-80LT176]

## ispLSI2128A-80LT176
designator U?
In-System Programmable High-Density PLD; Note: Pins 24, 25, 26 and 114 have dual function capability.
footprint TQFP176_N (Thin QFP, 176-Leads, Body 24x24mm, Pitch 0.5mm, IPC Medium Density)
footprint TQFP176_L (Thin QFP, 176-Leads, Body 24x24mm, Pitch 0.5mm, IPC High Density)
footprint TQFP176_M (Thin QFP, 176-Leads, Body 24x24mm, Pitch 0.5mm, IPC Low Density)
3D model 2128A-TQFP176 (176-Pin Thin Quad Flat Pack 0.5 mm Pitch)
part A pins: 2 I/O114 (io), 3 I/O115 (io), 4 I/O116 (io), 5 I/O117 (io), 6 I/O118 (io), 7 I/O119 (io), 8 I/O120 (io), 9 I/O121 (io), 12 I/O122 (io), 14 I/O123 (io), 15 I/O124 (io), 16 I/O125 (io), 17 I/O126 (io), 18 I/O127 (io), 19 Y0 (in), 21 Y1 (in), 22 ~{RESET} (in), 23 ~{ispEN} (in), 24 SDI/IN7 (in), 25 SCLK/IN0 (in), 26 MODE/IN1 (in), 27 I/O0 (io), 28 I/O1 (io), 31 I/O2 (io), 32 I/O3 (io), 33 I/O4 (io), 35 I/O5 (io), 36 I/O6 (io), 37 I/O7 (io), 38 I/O8 (io), 39 I/O9 (io), 41 I/O10 (io), 42 I/O11 (io), 43 I/O12 (io), 44 I/O13 (io), 45 I/O14 (io), 46 I/O15 (io), 47 I/O16 (io), 48 I/O17 (io), 50 I/O18 (io), 51 I/O19 (io), 52 I/O20 (io), 53 I/O21 (io), 55 I/O22 (io), 57 I/O23 (io), 58 I/O24 (io), 59 I/O25 (io), 60 I/O26 (io), 61 I/O27 (io), 62 I/O28 (io), 63 I/O29 (io), 65 I/O30 (io), 66 I/O31 (io), 67 I/O32 (io), 68 I/O33 (io), 70 I/O34 (io), 71 I/O35 (io), 72 I/O36 (io), 73 I/O37 (io), 75 I/O38 (io), 76 I/O39 (io), 77 I/O40 (io), 79 I/O41 (io), 80 I/O42 (io), 81 I/O43 (io), 82 I/O44 (io), 83 I/O45 (io), 85 I/O46 (io), 86 I/O47 (io), 87 I/O48 (io), 88 I/O49 (io), 90 I/O50 (io), 91 I/O51 (io), 92 I/O52 (io), 93 I/O53 (io), 94 I/O54 (io), 95 I/O55 (io), 96 I/O56 (io), 97 I/O57 (io), 99 I/O58 (io), 101 I/O59 (io), 102 I/O60 (io), 103 I/O61 (io), 104 I/O62 (io), 105 I/O63 (io), 106 IN2 (in), 107 IN3 (in), 109 GOE1 (in), 110 GOE0 (in), 111 Y2 (in), 112 IN4 (in), 113 IN5 (in), 114 SDO/IN6 (io), 115 I/O64 (io), 116 I/O65 (io), 119 I/O66 (io), 120 I/O67 (io), 121 I/O68 (io), 123 I/O69 (io), 124 I/O70 (io), 125 I/O71 (io), 126 I/O72 (io), 127 I/O73 (io), 129 I/O74 (io), 130 I/O75 (io), 131 I/O76 (io), 132 I/O77 (io), 133 I/O78 (io), 134 I/O79 (io), 135 I/O80 (io), 136 I/O81 (io), 138 I/O82 (io), 139 I/O83 (io), 140 I/O84 (io), 141 I/O85 (io), 143 I/O86 (io), 145 I/O87 (io), 146 I/O88 (io), 147 I/O89 (io), 148 I/O90 (io), 149 I/O91 (io), 150 I/O92 (io), 151 I/O93 (io), 153 I/O94 (io), 154 I/O95 (io), 155 I/O96 (io), 156 I/O97 (io), 158 I/O98 (io), 159 I/O99 (io), 160 I/O100 (io), 161 I/O101 (io), 163 I/O102 (io), 164 I/O103 (io), 165 I/O104 (io), 167 I/O105 (io), 168 I/O106 (io), 169 I/O107 (io), 170 I/O108 (io), 171 I/O109 (io), 173 I/O110 (io), 174 I/O111 (io), 175 I/O112 (io), 176 I/O113 (io)
part B pins: 1 GND (power), 10 NC, 11 GND (power), 13 VCC (power), 20 NC, 29 GND (power), 30 NC, 34 VCC (power), 40 NC, 49 GND (power), 54 NC, 56 VCC (power), 64 NC, 69 GND (power), 74 NC, 78 VCC (power), 84 NC, 89 GND (power), 98 NC, 100 VCC (power), 108 NC, 117 GND (power), 118 NC, 122 VCC (power), 128 NC, 137 GND (power), 142 NC, 144 VCC (power), 152 NC, 157 GND (power), 162 NC, 166 VCC (power), 172 NC

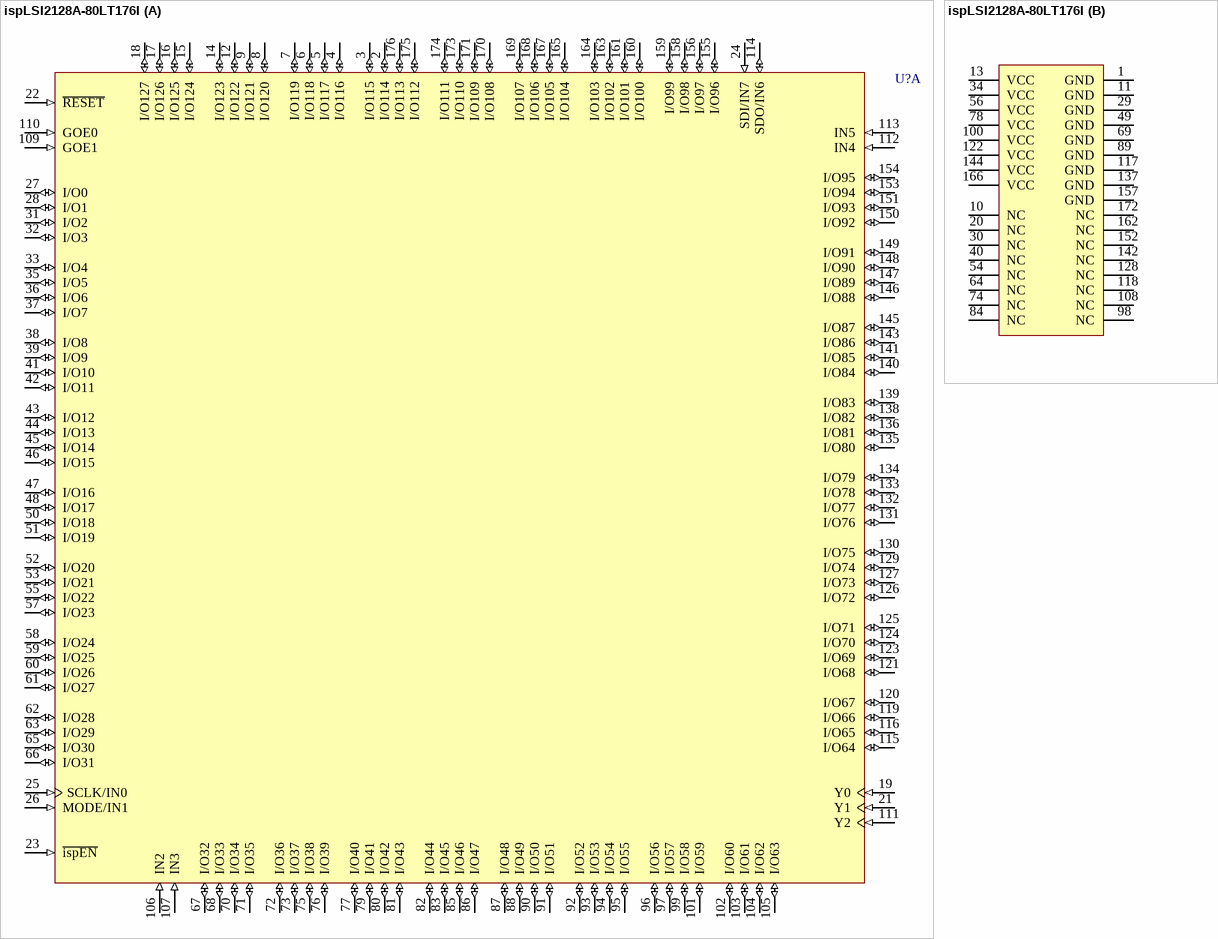
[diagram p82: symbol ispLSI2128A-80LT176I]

## ispLSI2128A-80LT176I
designator U?
In-System Programmable High-Density PLD; Note: Pins 24, 25, 26 and 114 have dual function capability.
footprint TQFP176_N (Thin QFP, 176-Leads, Body 24x24mm, Pitch 0.5mm, IPC Medium Density)
footprint TQFP176_L (Thin QFP, 176-Leads, Body 24x24mm, Pitch 0.5mm, IPC High Density)
footprint TQFP176_M (Thin QFP, 176-Leads, Body 24x24mm, Pitch 0.5mm, IPC Low Density)
3D model 2128A-TQFP176 (176-Pin Thin Quad Flat Pack 0.5 mm Pitch)
part A pins: 2 I/O114 (io), 3 I/O115 (io), 4 I/O116 (io), 5 I/O117 (io), 6 I/O118 (io), 7 I/O119 (io), 8 I/O120 (io), 9 I/O121 (io), 12 I/O122 (io), 14 I/O123 (io), 15 I/O124 (io), 16 I/O125 (io), 17 I/O126 (io), 18 I/O127 (io), 19 Y0 (in), 21 Y1 (in), 22 ~{RESET} (in), 23 ~{ispEN} (in), 24 SDI/IN7 (in), 25 SCLK/IN0 (in), 26 MODE/IN1 (in), 27 I/O0 (io), 28 I/O1 (io), 31 I/O2 (io), 32 I/O3 (io), 33 I/O4 (io), 35 I/O5 (io), 36 I/O6 (io), 37 I/O7 (io), 38 I/O8 (io), 39 I/O9 (io), 41 I/O10 (io), 42 I/O11 (io), 43 I/O12 (io), 44 I/O13 (io), 45 I/O14 (io), 46 I/O15 (io), 47 I/O16 (io), 48 I/O17 (io), 50 I/O18 (io), 51 I/O19 (io), 52 I/O20 (io), 53 I/O21 (io), 55 I/O22 (io), 57 I/O23 (io), 58 I/O24 (io), 59 I/O25 (io), 60 I/O26 (io), 61 I/O27 (io), 62 I/O28 (io), 63 I/O29 (io), 65 I/O30 (io), 66 I/O31 (io), 67 I/O32 (io), 68 I/O33 (io), 70 I/O34 (io), 71 I/O35 (io), 72 I/O36 (io), 73 I/O37 (io), 75 I/O38 (io), 76 I/O39 (io), 77 I/O40 (io), 79 I/O41 (io), 80 I/O42 (io), 81 I/O43 (io), 82 I/O44 (io), 83 I/O45 (io), 85 I/O46 (io), 86 I/O47 (io), 87 I/O48 (io), 88 I/O49 (io), 90 I/O50 (io), 91 I/O51 (io), 92 I/O52 (io), 93 I/O53 (io), 94 I/O54 (io), 95 I/O55 (io), 96 I/O56 (io), 97 I/O57 (io), 99 I/O58 (io), 101 I/O59 (io), 102 I/O60 (io), 103 I/O61 (io), 104 I/O62 (io), 105 I/O63 (io), 106 IN2 (in), 107 IN3 (in), 109 GOE1 (in), 110 GOE0 (in), 111 Y2 (in), 112 IN4 (in), 113 IN5 (in), 114 SDO/IN6 (io), 115 I/O64 (io), 116 I/O65 (io), 119 I/O66 (io), 120 I/O67 (io), 121 I/O68 (io), 123 I/O69 (io), 124 I/O70 (io), 125 I/O71 (io), 126 I/O72 (io), 127 I/O73 (io), 129 I/O74 (io), 130 I/O75 (io), 131 I/O76 (io), 132 I/O77 (io), 133 I/O78 (io), 134 I/O79 (io), 135 I/O80 (io), 136 I/O81 (io), 138 I/O82 (io), 139 I/O83 (io), 140 I/O84 (io), 141 I/O85 (io), 143 I/O86 (io), 145 I/O87 (io), 146 I/O88 (io), 147 I/O89 (io), 148 I/O90 (io), 149 I/O91 (io), 150 I/O92 (io), 151 I/O93 (io), 153 I/O94 (io), 154 I/O95 (io), 155 I/O96 (io), 156 I/O97 (io), 158 I/O98 (io), 159 I/O99 (io), 160 I/O100 (io), 161 I/O101 (io), 163 I/O102 (io), 164 I/O103 (io), 165 I/O104 (io), 167 I/O105 (io), 168 I/O106 (io), 169 I/O107 (io), 170 I/O108 (io), 171 I/O109 (io), 173 I/O110 (io), 174 I/O111 (io), 175 I/O112 (io), 176 I/O113 (io)
part B pins: 1 GND (power), 10 NC, 11 GND (power), 13 VCC (power), 20 NC, 29 GND (power), 30 NC, 34 VCC (power), 40 NC, 49 GND (power), 54 NC, 56 VCC (power), 64 NC, 69 GND (power), 74 NC, 78 VCC (power), 84 NC, 89 GND (power), 98 NC, 100 VCC (power), 108 NC, 117 GND (power), 118 NC, 122 VCC (power), 128 NC, 137 GND (power), 142 NC, 144 VCC (power), 152 NC, 157 GND (power), 162 NC, 166 VCC (power), 172 NC

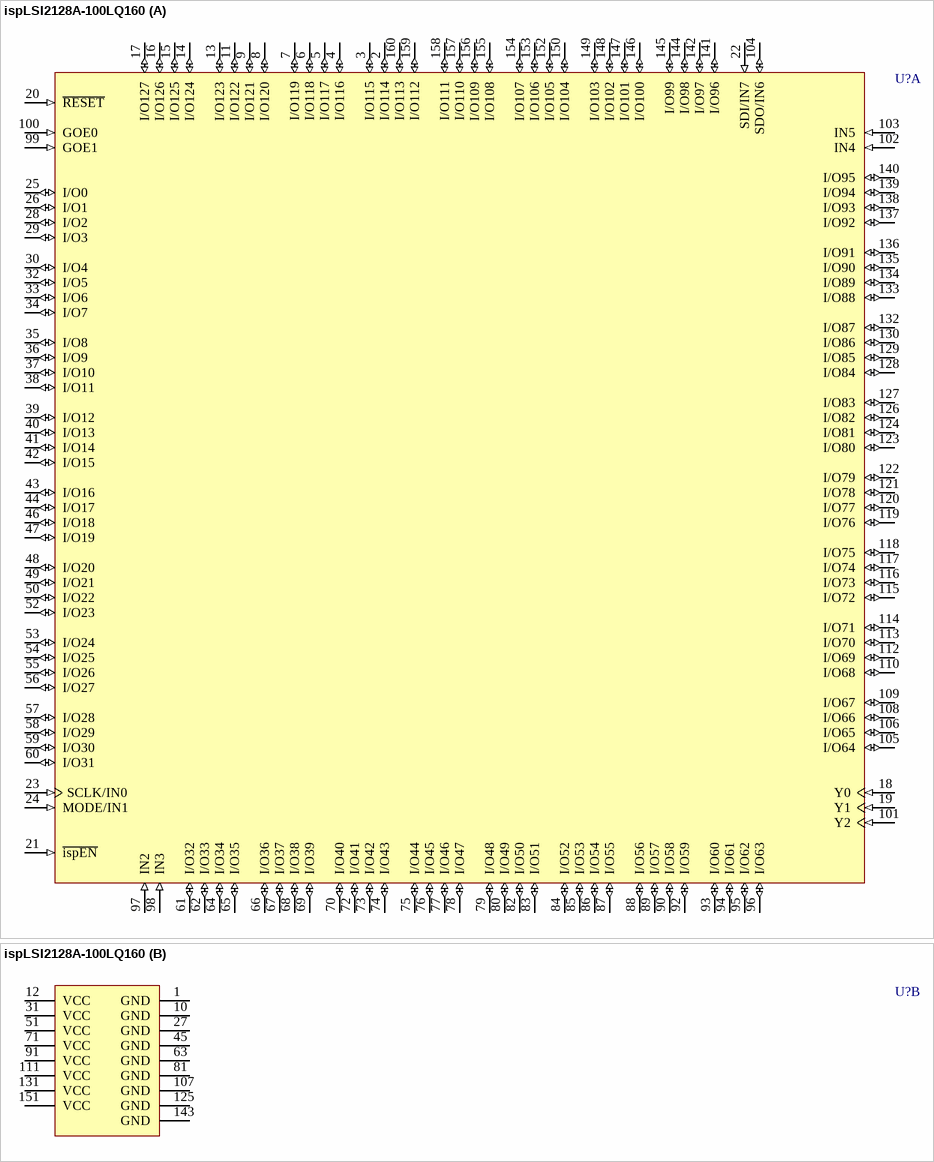
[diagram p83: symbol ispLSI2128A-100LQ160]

## ispLSI2128A-100LQ160
designator U?
In-System Programmable High-Density PLD; Note: Pins 22, 23, 24 and 104 have dual function capability.
footprint PQFP160_N (QFP, 160-Leads, Body 28 x 28mm, Pitch 0.65mm, IPC Medium Density)
footprint PQFP160_L (QFP, 160-Leads, Body 28 x 28mm, Pitch 0.65mm, IPC High Density)
footprint PQFP160_M (QFP, 160-Leads, Body 28 x 28mm, Pitch 0.65mm, IPC Low Density)
3D model 2128A-PQFP160 (160-Pin Quad Flat Pack 0.65 mm Pitch)
part A pins: 2 I/O114 (io), 3 I/O115 (io), 4 I/O116 (io), 5 I/O117 (io), 6 I/O118 (io), 7 I/O119 (io), 8 I/O120 (io), 9 I/O121 (io), 11 I/O122 (io), 13 I/O123 (io), 14 I/O124 (io), 15 I/O125 (io), 16 I/O126 (io), 17 I/O127 (io), 18 Y0 (in), 19 Y1 (in), 20 ~{RESET} (in), 21 ~{ispEN} (in), 22 SDI/IN7 (in), 23 SCLK/IN0 (in), 24 MODE/IN1 (in), 25 I/O0 (io), 26 I/O1 (io), 28 I/O2 (io), 29 I/O3 (io), 30 I/O4 (io), 32 I/O5 (io), 33 I/O6 (io), 34 I/O7 (io), 35 I/O8 (io), 36 I/O9 (io), 37 I/O10 (io), 38 I/O11 (io), 39 I/O12 (io), 40 I/O13 (io), 41 I/O14 (io), 42 I/O15 (io), 43 I/O16 (io), 44 I/O17 (io), 46 I/O18 (io), 47 I/O19 (io), 48 I/O20 (io), 49 I/O21 (io), 50 I/O22 (io), 52 I/O23 (io), 53 I/O24 (io), 54 I/O25 (io), 55 I/O26 (io), 56 I/O27 (io), 57 I/O28 (io), 58 I/O29 (io), 59 I/O30 (io), 60 I/O31 (io), 61 I/O32 (io), 62 I/O33 (io), 64 I/O34 (io), 65 I/O35 (io), 66 I/O36 (io), 67 I/O37 (io), 68 I/O38 (io), 69 I/O39 (io), 70 I/O40 (io), 72 I/O41 (io), 73 I/O42 (io), 74 I/O43 (io), 75 I/O44 (io), 76 I/O45 (io), 77 I/O46 (io), 78 I/O47 (io), 79 I/O48 (io), 80 I/O49 (io), 82 I/O50 (io), 83 I/O51 (io), 84 I/O52 (io), 85 I/O53 (io), 86 I/O54 (io), 87 I/O55 (io), 88 I/O56 (io), 89 I/O57 (io), 90 I/O58 (io), 92 I/O59 (io), 93 I/O60 (io), 94 I/O61 (io), 95 I/O62 (io), 96 I/O63 (io), 97 IN2 (in), 98 IN3 (in), 99 GOE1 (in), 100 GOE0 (in), 101 Y2 (in), 102 IN4 (in), 103 IN5 (in), 104 SDO/IN6 (io), 105 I/O64 (io), 106 I/O65 (io), 108 I/O66 (io), 109 I/O67 (io), 110 I/O68 (io), 112 I/O69 (io), 113 I/O70 (io), 114 I/O71 (io), 115 I/O72 (io), 116 I/O73 (io), 117 I/O74 (io), 118 I/O75 (io), 119 I/O76 (io), 120 I/O77 (io), 121 I/O78 (io), 122 I/O79 (io), 123 I/O80 (io), 124 I/O81 (io), 126 I/O82 (io), 127 I/O83 (io), 128 I/O84 (io), 129 I/O85 (io), 130 I/O86 (io), 132 I/O87 (io), 133 I/O88 (io), 134 I/O89 (io), 135 I/O90 (io), 136 I/O91 (io), 137 I/O92 (io), 138 I/O93 (io), 139 I/O94 (io), 140 I/O95 (io), 141 I/O96 (io), 142 I/O97 (io), 144 I/O98 (io), 145 I/O99 (io), 146 I/O100 (io), 147 I/O101 (io), 148 I/O102 (io), 149 I/O103 (io), 150 I/O104 (io), 152 I/O105 (io), 153 I/O106 (io), 154 I/O107 (io), 155 I/O108 (io), 156 I/O109 (io), 157 I/O110 (io), 158 I/O111 (io), 159 I/O112 (io), 160 I/O113 (io)
part B pins: 1 GND (power), 10 GND (power), 12 VCC (power), 27 GND (power), 31 VCC (power), 45 GND (power), 51 VCC (power), 63 GND (power), 71 VCC (power), 81 GND (power), 91 VCC (power), 107 GND (power), 111 VCC (power), 125 GND (power), 131 VCC (power), 143 GND (power), 151 VCC (power)

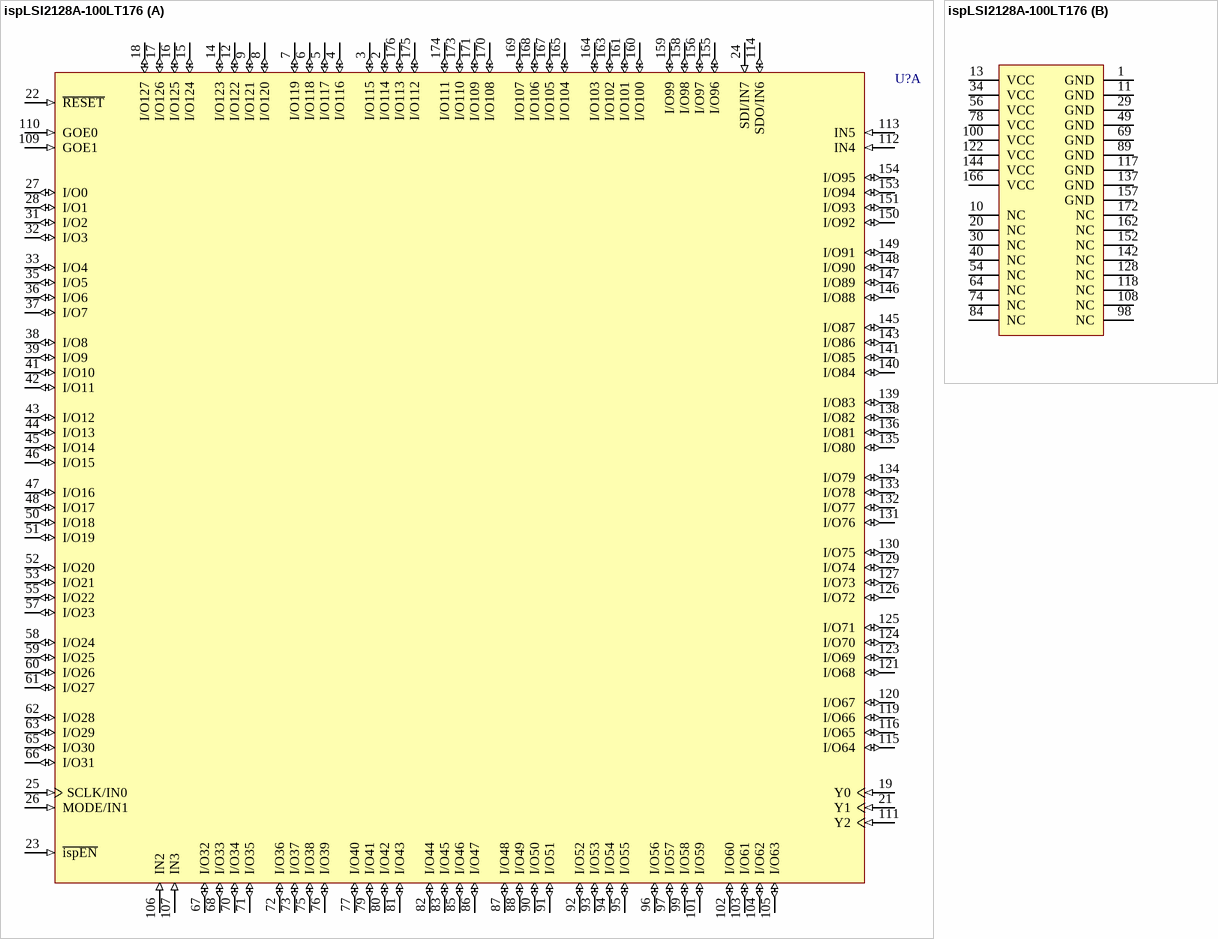
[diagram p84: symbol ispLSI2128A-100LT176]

## ispLSI2128A-100LT176
designator U?
In-System Programmable High-Density PLD; Note: Pins 24, 25, 26 and 114 have dual function capability.
footprint TQFP176_N (Thin QFP, 176-Leads, Body 24x24mm, Pitch 0.5mm, IPC Medium Density)
footprint TQFP176_L (Thin QFP, 176-Leads, Body 24x24mm, Pitch 0.5mm, IPC High Density)
footprint TQFP176_M (Thin QFP, 176-Leads, Body 24x24mm, Pitch 0.5mm, IPC Low Density)
3D model 2128A-TQFP176 (176-Pin Thin Quad Flat Pack 0.5 mm Pitch)
part A pins: 2 I/O114 (io), 3 I/O115 (io), 4 I/O116 (io), 5 I/O117 (io), 6 I/O118 (io), 7 I/O119 (io), 8 I/O120 (io), 9 I/O121 (io), 12 I/O122 (io), 14 I/O123 (io), 15 I/O124 (io), 16 I/O125 (io), 17 I/O126 (io), 18 I/O127 (io), 19 Y0 (in), 21 Y1 (in), 22 ~{RESET} (in), 23 ~{ispEN} (in), 24 SDI/IN7 (in), 25 SCLK/IN0 (in), 26 MODE/IN1 (in), 27 I/O0 (io), 28 I/O1 (io), 31 I/O2 (io), 32 I/O3 (io), 33 I/O4 (io), 35 I/O5 (io), 36 I/O6 (io), 37 I/O7 (io), 38 I/O8 (io), 39 I/O9 (io), 41 I/O10 (io), 42 I/O11 (io), 43 I/O12 (io), 44 I/O13 (io), 45 I/O14 (io), 46 I/O15 (io), 47 I/O16 (io), 48 I/O17 (io), 50 I/O18 (io), 51 I/O19 (io), 52 I/O20 (io), 53 I/O21 (io), 55 I/O22 (io), 57 I/O23 (io), 58 I/O24 (io), 59 I/O25 (io), 60 I/O26 (io), 61 I/O27 (io), 62 I/O28 (io), 63 I/O29 (io), 65 I/O30 (io), 66 I/O31 (io), 67 I/O32 (io), 68 I/O33 (io), 70 I/O34 (io), 71 I/O35 (io), 72 I/O36 (io), 73 I/O37 (io), 75 I/O38 (io), 76 I/O39 (io), 77 I/O40 (io), 79 I/O41 (io), 80 I/O42 (io), 81 I/O43 (io), 82 I/O44 (io), 83 I/O45 (io), 85 I/O46 (io), 86 I/O47 (io), 87 I/O48 (io), 88 I/O49 (io), 90 I/O50 (io), 91 I/O51 (io), 92 I/O52 (io), 93 I/O53 (io), 94 I/O54 (io), 95 I/O55 (io), 96 I/O56 (io), 97 I/O57 (io), 99 I/O58 (io), 101 I/O59 (io), 102 I/O60 (io), 103 I/O61 (io), 104 I/O62 (io), 105 I/O63 (io), 106 IN2 (in), 107 IN3 (in), 109 GOE1 (in), 110 GOE0 (in), 111 Y2 (in), 112 IN4 (in), 113 IN5 (in), 114 SDO/IN6 (io), 115 I/O64 (io), 116 I/O65 (io), 119 I/O66 (io), 120 I/O67 (io), 121 I/O68 (io), 123 I/O69 (io), 124 I/O70 (io), 125 I/O71 (io), 126 I/O72 (io), 127 I/O73 (io), 129 I/O74 (io), 130 I/O75 (io), 131 I/O76 (io), 132 I/O77 (io), 133 I/O78 (io), 134 I/O79 (io), 135 I/O80 (io), 136 I/O81 (io), 138 I/O82 (io), 139 I/O83 (io), 140 I/O84 (io), 141 I/O85 (io), 143 I/O86 (io), 145 I/O87 (io), 146 I/O88 (io), 147 I/O89 (io), 148 I/O90 (io), 149 I/O91 (io), 150 I/O92 (io), 151 I/O93 (io), 153 I/O94 (io), 154 I/O95 (io), 155 I/O96 (io), 156 I/O97 (io), 158 I/O98 (io), 159 I/O99 (io), 160 I/O100 (io), 161 I/O101 (io), 163 I/O102 (io), 164 I/O103 (io), 165 I/O104 (io), 167 I/O105 (io), 168 I/O106 (io), 169 I/O107 (io), 170 I/O108 (io), 171 I/O109 (io), 173 I/O110 (io), 174 I/O111 (io), 175 I/O112 (io), 176 I/O113 (io)
part B pins: 1 GND (power), 10 NC, 11 GND (power), 13 VCC (power), 20 NC, 29 GND (power), 30 NC, 34 VCC (power), 40 NC, 49 GND (power), 54 NC, 56 VCC (power), 64 NC, 69 GND (power), 74 NC, 78 VCC (power), 84 NC, 89 GND (power), 98 NC, 100 VCC (power), 108 NC, 117 GND (power), 118 NC, 122 VCC (power), 128 NC, 137 GND (power), 142 NC, 144 VCC (power), 152 NC, 157 GND (power), 162 NC, 166 VCC (power), 172 NC

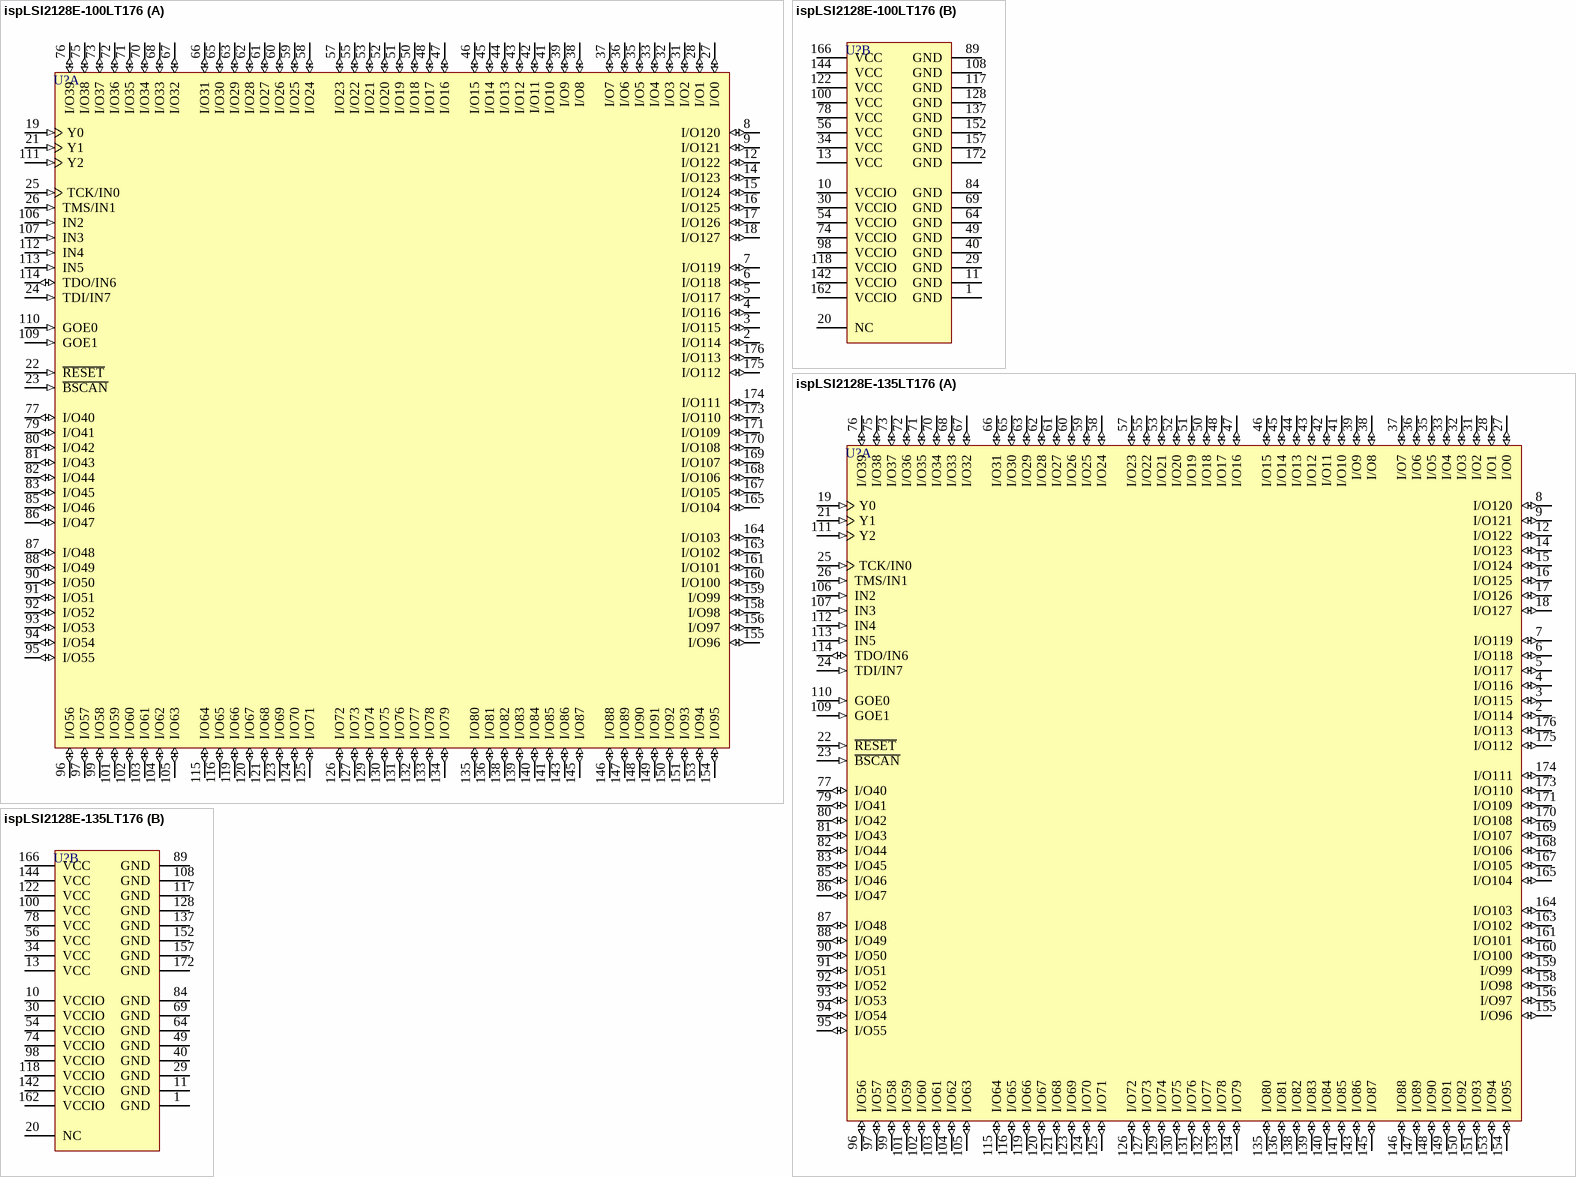
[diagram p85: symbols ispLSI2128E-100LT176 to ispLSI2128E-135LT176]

## ispLSI2128E-100LT176
designator U?
In-System Programmable SuperFAST High Density PLD
footprint TQFP176_N (Thin QFP, 176-Leads, Body 24x24mm, Pitch 0.5mm, IPC Medium Density)
footprint TQFP176_L (Thin QFP, 176-Leads, Body 24x24mm, Pitch 0.5mm, IPC High Density)
footprint TQFP176_M (Thin QFP, 176-Leads, Body 24x24mm, Pitch 0.5mm, IPC Low Density)
3D model 2128E-TQFP176 (176-Pin Thin Quad Flat Pack 0.5 mm Pitch)
part A pins: 2 I/O114 (io), 3 I/O115 (io), 4 I/O116 (io), 5 I/O117 (io), 6 I/O118 (io), 7 I/O119 (io), 8 I/O120 (io), 9 I/O121 (io), 12 I/O122 (io), 14 I/O123 (io), 15 I/O124 (io), 16 I/O125 (io), 17 I/O126 (io), 18 I/O127 (io), 19 Y0 (in), 21 Y1 (in), 22 ~{RESET} (in), 23 ~{BSCAN} (in), 24 TDI/IN7 (in), 25 TCK/IN0 (in), 26 TMS/IN1 (in), 27 I/O0 (io), 28 I/O1 (io), 31 I/O2 (io), 32 I/O3 (io), 33 I/O4 (io), 35 I/O5 (io), 36 I/O6 (io), 37 I/O7 (io), 38 I/O8 (io), 39 I/O9 (io), 41 I/O10 (io), 42 I/O11 (io), 43 I/O12 (io), 44 I/O13 (io), 45 I/O14 (io), 46 I/O15 (io), 47 I/O16 (io), 48 I/O17 (io), 50 I/O18 (io), 51 I/O19 (io), 52 I/O20 (io), 53 I/O21 (io), 55 I/O22 (io), 57 I/O23 (io), 58 I/O24 (io), 59 I/O25 (io), 60 I/O26 (io), 61 I/O27 (io), 62 I/O28 (io), 63 I/O29 (io), 65 I/O30 (io), 66 I/O31 (io), 67 I/O32 (io), 68 I/O33 (io), 70 I/O34 (io), 71 I/O35 (io), 72 I/O36 (io), 73 I/O37 (io), 75 I/O38 (io), 76 I/O39 (io), 77 I/O40 (io), 79 I/O41 (io), 80 I/O42 (io), 81 I/O43 (io), 82 I/O44 (io), 83 I/O45 (io), 85 I/O46 (io), 86 I/O47 (io), 87 I/O48 (io), 88 I/O49 (io), 90 I/O50 (io), 91 I/O51 (io), 92 I/O52 (io), 93 I/O53 (io), 94 I/O54 (io), 95 I/O55 (io), 96 I/O56 (io), 97 I/O57 (io), 99 I/O58 (io), 101 I/O59 (io), 102 I/O60 (io), 103 I/O61 (io), 104 I/O62 (io), 105 I/O63 (io), 106 IN2 (in), 107 IN3 (in), 109 GOE1 (in), 110 GOE0 (in), 111 Y2 (in), 112 IN4 (in), 113 IN5 (in), 114 TDO/IN6 (io), 115 I/O64 (io), 116 I/O65 (io), 119 I/O66 (io), 120 I/O67 (io), 121 I/O68 (io), 123 I/O69 (io), 124 I/O70 (io), 125 I/O71 (io), 126 I/O72 (io), 127 I/O73 (io), 129 I/O74 (io), 130 I/O75 (io), 131 I/O76 (io), 132 I/O77 (io), 133 I/O78 (io), 134 I/O79 (io), 135 I/O80 (io), 136 I/O81 (io), 138 I/O82 (io), 139 I/O83 (io), 140 I/O84 (io), 141 I/O85 (io), 143 I/O86 (io), 145 I/O87 (io), 146 I/O88 (io), 147 I/O89 (io), 148 I/O90 (io), 149 I/O91 (io), 150 I/O92 (io), 151 I/O93 (io), 153 I/O94 (io), 154 I/O95 (io), 155 I/O96 (io), 156 I/O97 (io), 158 I/O98 (io), 159 I/O99 (io), 160 I/O100 (io), 161 I/O101 (io), 163 I/O102 (io), 164 I/O103 (io), 165 I/O104 (io), 167 I/O105 (io), 168 I/O106 (io), 169 I/O107 (io), 170 I/O108 (io), 171 I/O109 (io), 173 I/O110 (io), 174 I/O111 (io), 175 I/O112 (io), 176 I/O113 (io)
part B pins: 1 GND (power), 10 VCCIO (power), 11 GND (power), 13 VCC (power), 20 NC, 29 GND (power), 30 VCCIO (power), 34 VCC (power), 40 GND (power), 49 GND (power), 54 VCCIO (power), 56 VCC (power), 64 GND (power), 69 GND (power), 74 VCCIO (power), 78 VCC (power), 84 GND (power), 89 GND (power), 98 VCCIO (power), 100 VCC (power), 108 GND (power), 117 GND (power), 118 VCCIO (power), 122 VCC (power), 128 GND (power), 137 GND (power), 142 VCCIO (power), 144 VCC (power), 152 GND (power), 157 GND (power), 162 VCCIO (power), 166 VCC (power), 172 GND (power)

## ispLSI2128E-135LT176
designator U?
In-System Programmable SuperFAST High Density PLD
footprint TQFP176_N (Thin QFP, 176-Leads, Body 24x24mm, Pitch 0.5mm, IPC Medium Density)
footprint TQFP176_L (Thin QFP, 176-Leads, Body 24x24mm, Pitch 0.5mm, IPC High Density)
footprint TQFP176_M (Thin QFP, 176-Leads, Body 24x24mm, Pitch 0.5mm, IPC Low Density)
3D model 2128E-TQFP176 (176-Pin Thin Quad Flat Pack 0.5 mm Pitch)
part A pins: 2 I/O114 (io), 3 I/O115 (io), 4 I/O116 (io), 5 I/O117 (io), 6 I/O118 (io), 7 I/O119 (io), 8 I/O120 (io), 9 I/O121 (io), 12 I/O122 (io), 14 I/O123 (io), 15 I/O124 (io), 16 I/O125 (io), 17 I/O126 (io), 18 I/O127 (io), 19 Y0 (in), 21 Y1 (in), 22 ~{RESET} (in), 23 ~{BSCAN} (in), 24 TDI/IN7 (in), 25 TCK/IN0 (in), 26 TMS/IN1 (in), 27 I/O0 (io), 28 I/O1 (io), 31 I/O2 (io), 32 I/O3 (io), 33 I/O4 (io), 35 I/O5 (io), 36 I/O6 (io), 37 I/O7 (io), 38 I/O8 (io), 39 I/O9 (io), 41 I/O10 (io), 42 I/O11 (io), 43 I/O12 (io), 44 I/O13 (io), 45 I/O14 (io), 46 I/O15 (io), 47 I/O16 (io), 48 I/O17 (io), 50 I/O18 (io), 51 I/O19 (io), 52 I/O20 (io), 53 I/O21 (io), 55 I/O22 (io), 57 I/O23 (io), 58 I/O24 (io), 59 I/O25 (io), 60 I/O26 (io), 61 I/O27 (io), 62 I/O28 (io), 63 I/O29 (io), 65 I/O30 (io), 66 I/O31 (io), 67 I/O32 (io), 68 I/O33 (io), 70 I/O34 (io), 71 I/O35 (io), 72 I/O36 (io), 73 I/O37 (io), 75 I/O38 (io), 76 I/O39 (io), 77 I/O40 (io), 79 I/O41 (io), 80 I/O42 (io), 81 I/O43 (io), 82 I/O44 (io), 83 I/O45 (io), 85 I/O46 (io), 86 I/O47 (io), 87 I/O48 (io), 88 I/O49 (io), 90 I/O50 (io), 91 I/O51 (io), 92 I/O52 (io), 93 I/O53 (io), 94 I/O54 (io), 95 I/O55 (io), 96 I/O56 (io), 97 I/O57 (io), 99 I/O58 (io), 101 I/O59 (io), 102 I/O60 (io), 103 I/O61 (io), 104 I/O62 (io), 105 I/O63 (io), 106 IN2 (in), 107 IN3 (in), 109 GOE1 (in), 110 GOE0 (in), 111 Y2 (in), 112 IN4 (in), 113 IN5 (in), 114 TDO/IN6 (io), 115 I/O64 (io), 116 I/O65 (io), 119 I/O66 (io), 120 I/O67 (io), 121 I/O68 (io), 123 I/O69 (io), 124 I/O70 (io), 125 I/O71 (io), 126 I/O72 (io), 127 I/O73 (io), 129 I/O74 (io), 130 I/O75 (io), 131 I/O76 (io), 132 I/O77 (io), 133 I/O78 (io), 134 I/O79 (io), 135 I/O80 (io), 136 I/O81 (io), 138 I/O82 (io), 139 I/O83 (io), 140 I/O84 (io), 141 I/O85 (io), 143 I/O86 (io), 145 I/O87 (io), 146 I/O88 (io), 147 I/O89 (io), 148 I/O90 (io), 149 I/O91 (io), 150 I/O92 (io), 151 I/O93 (io), 153 I/O94 (io), 154 I/O95 (io), 155 I/O96 (io), 156 I/O97 (io), 158 I/O98 (io), 159 I/O99 (io), 160 I/O100 (io), 161 I/O101 (io), 163 I/O102 (io), 164 I/O103 (io), 165 I/O104 (io), 167 I/O105 (io), 168 I/O106 (io), 169 I/O107 (io), 170 I/O108 (io), 171 I/O109 (io), 173 I/O110 (io), 174 I/O111 (io), 175 I/O112 (io), 176 I/O113 (io)
part B pins: 1 GND (power), 10 VCCIO (power), 11 GND (power), 13 VCC (power), 20 NC, 29 GND (power), 30 VCCIO (power), 34 VCC (power), 40 GND (power), 49 GND (power), 54 VCCIO (power), 56 VCC (power), 64 GND (power), 69 GND (power), 74 VCCIO (power), 78 VCC (power), 84 GND (power), 89 GND (power), 98 VCCIO (power), 100 VCC (power), 108 GND (power), 117 GND (power), 118 VCCIO (power), 122 VCC (power), 128 GND (power), 137 GND (power), 142 VCCIO (power), 144 VCC (power), 152 GND (power), 157 GND (power), 162 VCCIO (power), 166 VCC (power), 172 GND (power)

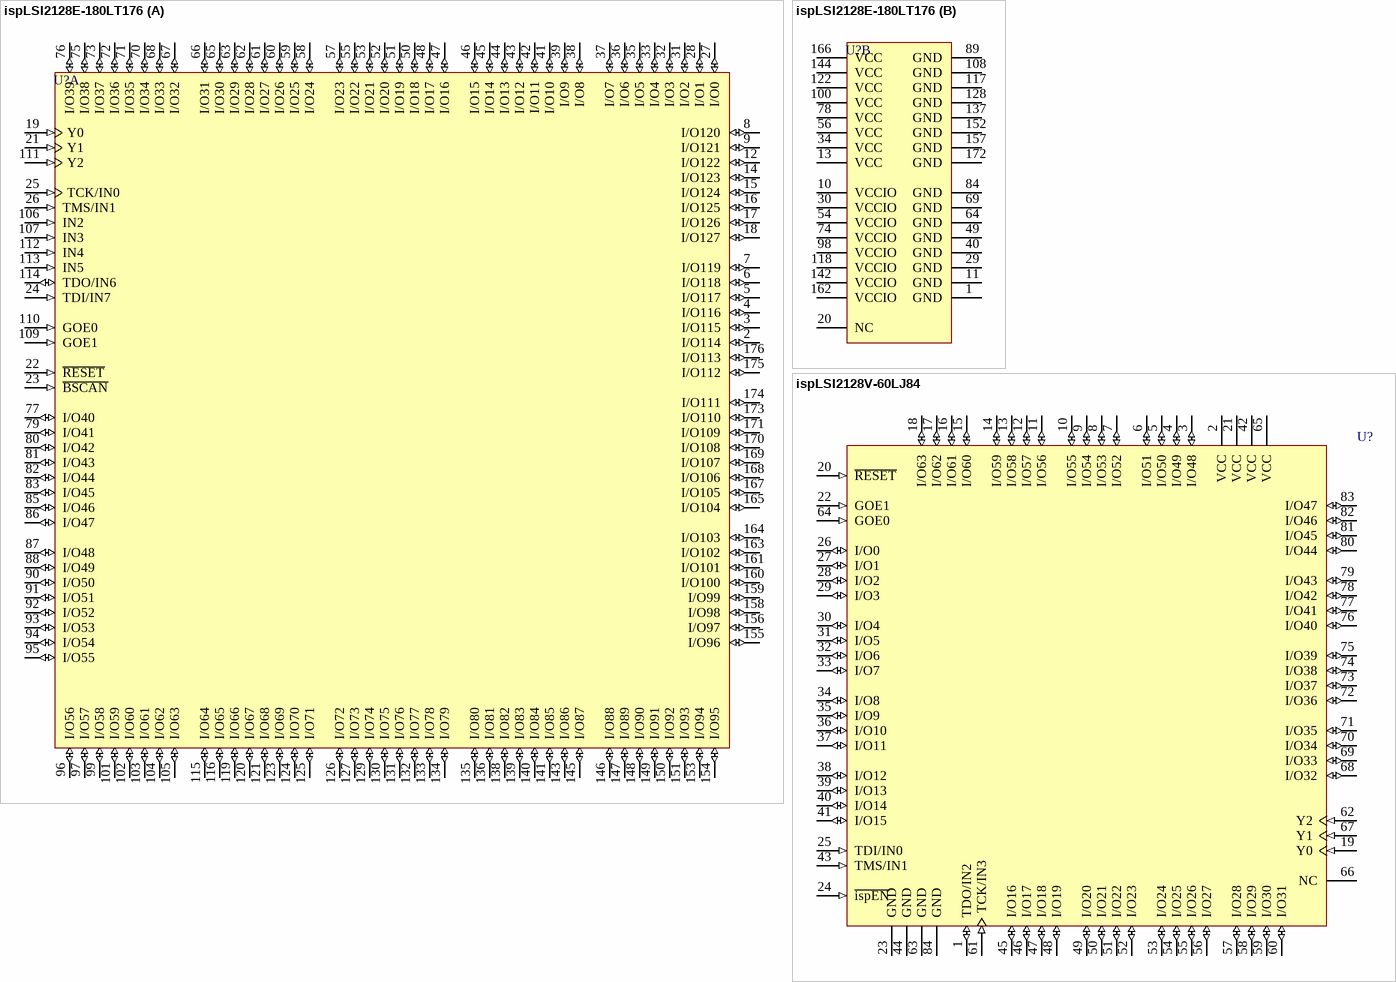
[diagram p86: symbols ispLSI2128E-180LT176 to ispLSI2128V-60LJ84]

## ispLSI2128E-180LT176
designator U?
In-System Programmable SuperFAST High Density PLD
footprint TQFP176_N (Thin QFP, 176-Leads, Body 24x24mm, Pitch 0.5mm, IPC Medium Density)
footprint TQFP176_L (Thin QFP, 176-Leads, Body 24x24mm, Pitch 0.5mm, IPC High Density)
footprint TQFP176_M (Thin QFP, 176-Leads, Body 24x24mm, Pitch 0.5mm, IPC Low Density)
3D model 2128E-TQFP176 (176-Pin Thin Quad Flat Pack 0.5 mm Pitch)
part A pins: 2 I/O114 (io), 3 I/O115 (io), 4 I/O116 (io), 5 I/O117 (io), 6 I/O118 (io), 7 I/O119 (io), 8 I/O120 (io), 9 I/O121 (io), 12 I/O122 (io), 14 I/O123 (io), 15 I/O124 (io), 16 I/O125 (io), 17 I/O126 (io), 18 I/O127 (io), 19 Y0 (in), 21 Y1 (in), 22 ~{RESET} (in), 23 ~{BSCAN} (in), 24 TDI/IN7 (in), 25 TCK/IN0 (in), 26 TMS/IN1 (in), 27 I/O0 (io), 28 I/O1 (io), 31 I/O2 (io), 32 I/O3 (io), 33 I/O4 (io), 35 I/O5 (io), 36 I/O6 (io), 37 I/O7 (io), 38 I/O8 (io), 39 I/O9 (io), 41 I/O10 (io), 42 I/O11 (io), 43 I/O12 (io), 44 I/O13 (io), 45 I/O14 (io), 46 I/O15 (io), 47 I/O16 (io), 48 I/O17 (io), 50 I/O18 (io), 51 I/O19 (io), 52 I/O20 (io), 53 I/O21 (io), 55 I/O22 (io), 57 I/O23 (io), 58 I/O24 (io), 59 I/O25 (io), 60 I/O26 (io), 61 I/O27 (io), 62 I/O28 (io), 63 I/O29 (io), 65 I/O30 (io), 66 I/O31 (io), 67 I/O32 (io), 68 I/O33 (io), 70 I/O34 (io), 71 I/O35 (io), 72 I/O36 (io), 73 I/O37 (io), 75 I/O38 (io), 76 I/O39 (io), 77 I/O40 (io), 79 I/O41 (io), 80 I/O42 (io), 81 I/O43 (io), 82 I/O44 (io), 83 I/O45 (io), 85 I/O46 (io), 86 I/O47 (io), 87 I/O48 (io), 88 I/O49 (io), 90 I/O50 (io), 91 I/O51 (io), 92 I/O52 (io), 93 I/O53 (io), 94 I/O54 (io), 95 I/O55 (io), 96 I/O56 (io), 97 I/O57 (io), 99 I/O58 (io), 101 I/O59 (io), 102 I/O60 (io), 103 I/O61 (io), 104 I/O62 (io), 105 I/O63 (io), 106 IN2 (in), 107 IN3 (in), 109 GOE1 (in), 110 GOE0 (in), 111 Y2 (in), 112 IN4 (in), 113 IN5 (in), 114 TDO/IN6 (io), 115 I/O64 (io), 116 I/O65 (io), 119 I/O66 (io), 120 I/O67 (io), 121 I/O68 (io), 123 I/O69 (io), 124 I/O70 (io), 125 I/O71 (io), 126 I/O72 (io), 127 I/O73 (io), 129 I/O74 (io), 130 I/O75 (io), 131 I/O76 (io), 132 I/O77 (io), 133 I/O78 (io), 134 I/O79 (io), 135 I/O80 (io), 136 I/O81 (io), 138 I/O82 (io), 139 I/O83 (io), 140 I/O84 (io), 141 I/O85 (io), 143 I/O86 (io), 145 I/O87 (io), 146 I/O88 (io), 147 I/O89 (io), 148 I/O90 (io), 149 I/O91 (io), 150 I/O92 (io), 151 I/O93 (io), 153 I/O94 (io), 154 I/O95 (io), 155 I/O96 (io), 156 I/O97 (io), 158 I/O98 (io), 159 I/O99 (io), 160 I/O100 (io), 161 I/O101 (io), 163 I/O102 (io), 164 I/O103 (io), 165 I/O104 (io), 167 I/O105 (io), 168 I/O106 (io), 169 I/O107 (io), 170 I/O108 (io), 171 I/O109 (io), 173 I/O110 (io), 174 I/O111 (io), 175 I/O112 (io), 176 I/O113 (io)
part B pins: 1 GND (power), 10 VCCIO (power), 11 GND (power), 13 VCC (power), 20 NC, 29 GND (power), 30 VCCIO (power), 34 VCC (power), 40 GND (power), 49 GND (power), 54 VCCIO (power), 56 VCC (power), 64 GND (power), 69 GND (power), 74 VCCIO (power), 78 VCC (power), 84 GND (power), 89 GND (power), 98 VCCIO (power), 100 VCC (power), 108 GND (power), 117 GND (power), 118 VCCIO (power), 122 VCC (power), 128 GND (power), 137 GND (power), 142 VCCIO (power), 144 VCC (power), 152 GND (power), 157 GND (power), 162 VCCIO (power), 166 VCC (power), 172 GND (power)

## ispLSI2128V-60LJ84
designator U?
3.3V High-Density Programmable Logic
footprint PLCC84_N (Leaded Chip Carrier, 84-Leads, Body 29.3x29.3mm, Pitch 1.27mm, IPC Medium Density)
footprint PLCC84_L (Leaded Chip Carrier, 84-Leads, Body 29.3x29.3mm, Pitch 1.27mm, IPC High Density)
footprint PLCC84_M (Leaded Chip Carrier, 84-Leads, Body 29.3x29.3mm, Pitch 1.27mm, IPC Low Density)
3D model 2128V-PLCC84 (84-Pin Leaded Chip Carrier 1.27 mm Pitch)
pins: 1 TDO/IN2 (io), 2 VCC (power), 3 I/O48 (io), 4 I/O49 (io), 5 I/O50 (io), 6 I/O51 (io), 7 I/O52 (io), 8 I/O53 (io), 9 I/O54 (io), 10 I/O55 (io), 11 I/O56 (io), 12 I/O57 (io), 13 I/O58 (io), 14 I/O59 (io), 15 I/O60 (io), 16 I/O61 (io), 17 I/O62 (io), 18 I/O63 (io), 19 Y0 (in), 20 ~{RESET} (in), 21 VCC (power), 22 GOE1 (in), 23 GND (power), 24 ~{isp}~{EN} (in), 25 TDI/IN0 (in), 26 I/O0 (io), 27 I/O1 (io), 28 I/O2 (io), 29 I/O3 (io), 30 I/O4 (io), 31 I/O5 (io), 32 I/O6 (io), 33 I/O7 (io), 34 I/O8 (io), 35 I/O9 (io), 36 I/O10 (io), 37 I/O11 (io), 38 I/O12 (io), 39 I/O13 (io), 40 I/O14 (io), 41 I/O15 (io), 42 VCC (power), 43 TMS/IN1 (in), 44 GND (power), 45 I/O16 (io), 46 I/O17 (io), 47 I/O18 (io), 48 I/O19 (io), 49 I/O20 (io), 50 I/O21 (io), 51 I/O22 (io), 52 I/O23 (io), 53 I/O24 (io), 54 I/O25 (io), 55 I/O26 (io), 56 I/O27 (io), 57 I/O28 (io), 58 I/O29 (io), 59 I/O30 (io), 60 I/O31 (io), 61 TCK/IN3 (in), 62 Y2 (in), 63 GND (power), 64 GOE0 (in), 65 VCC (power), 66 NC, 67 Y1 (in), 68 I/O32 (io), 69 I/O33 (io), 70 I/O34 (io), 71 I/O35 (io), 72 I/O36 (io), 73 I/O37 (io), 74 I/O38 (io), 75 I/O39 (io), 76 I/O40 (io), 77 I/O41 (io), 78 I/O42 (io), 79 I/O43 (io), 80 I/O44 (io), 81 I/O45 (io), 82 I/O46 (io), 83 I/O47 (io), 84 GND (power)

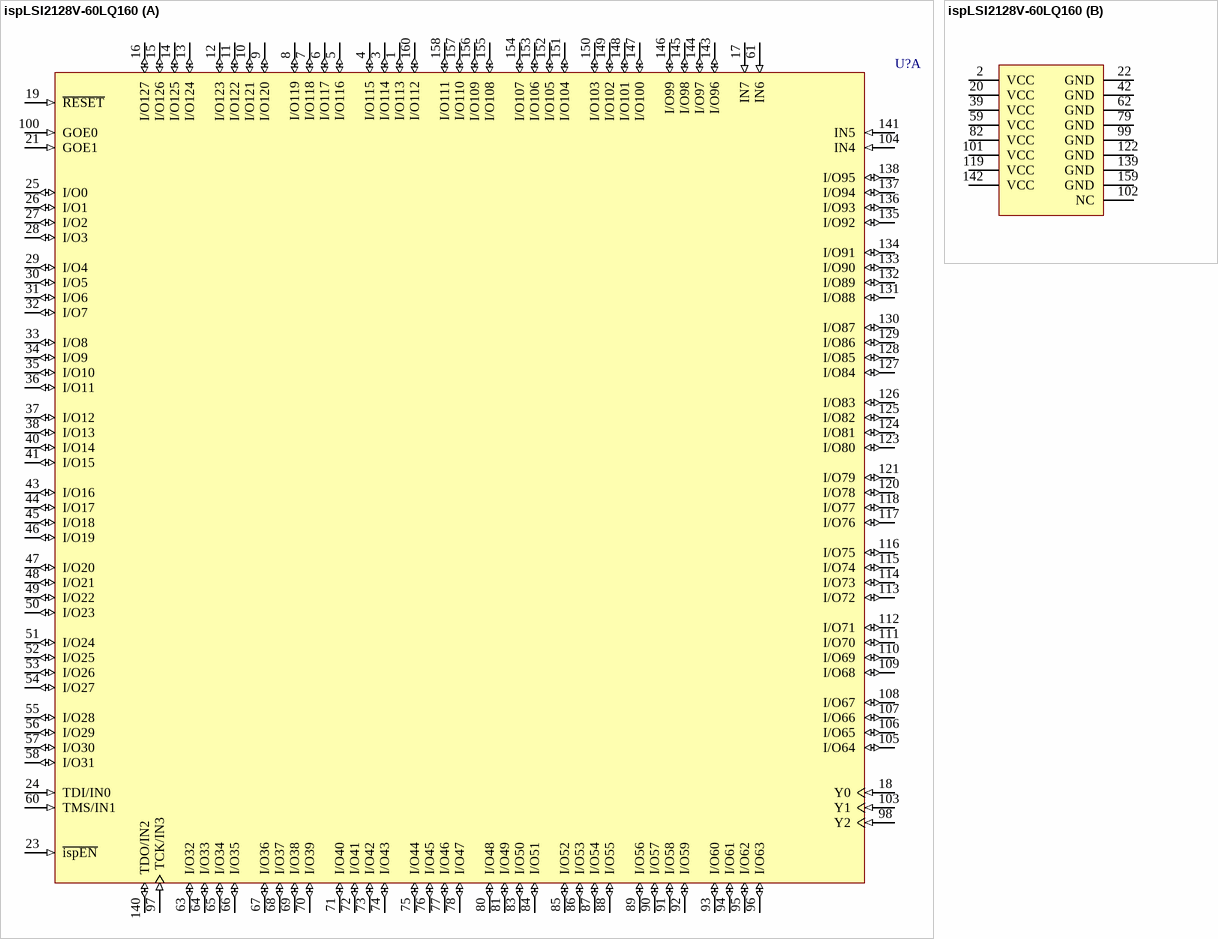
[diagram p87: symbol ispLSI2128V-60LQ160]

## ispLSI2128V-60LQ160
designator U?
3.3V High-Density Programmable Logic
footprint PQFP160_N (QFP, 160-Leads, Body 28 x 28mm, Pitch 0.65mm, IPC Medium Density)
footprint PQFP160_L (QFP, 160-Leads, Body 28 x 28mm, Pitch 0.65mm, IPC High Density)
footprint PQFP160_M (QFP, 160-Leads, Body 28 x 28mm, Pitch 0.65mm, IPC Low Density)
3D model 2128V-PQFP160 (160-Pin Quad Flat Pack 0.65 mm Pitch)
part A pins: 1 I/O113 (io), 3 I/O114 (io), 4 I/O115 (io), 5 I/O116 (io), 6 I/O117 (io), 7 I/O118 (io), 8 I/O119 (io), 9 I/O120 (io), 10 I/O121 (io), 11 I/O122 (io), 12 I/O123 (io), 13 I/O124 (io), 14 I/O125 (io), 15 I/O126 (io), 16 I/O127 (io), 17 IN7 (in), 18 Y0 (in), 19 ~{RESET} (in), 21 GOE1 (in), 23 ~{ispEN} (in), 24 TDI/IN0 (in), 25 I/O0 (io), 26 I/O1 (io), 27 I/O2 (io), 28 I/O3 (io), 29 I/O4 (io), 30 I/O5 (io), 31 I/O6 (io), 32 I/O7 (io), 33 I/O8 (io), 34 I/O9 (io), 35 I/O10 (io), 36 I/O11 (io), 37 I/O12 (io), 38 I/O13 (io), 40 I/O14 (io), 41 I/O15 (io), 43 I/O16 (io), 44 I/O17 (io), 45 I/O18 (io), 46 I/O19 (io), 47 I/O20 (io), 48 I/O21 (io), 49 I/O22 (io), 50 I/O23 (io), 51 I/O24 (io), 52 I/O25 (io), 53 I/O26 (io), 54 I/O27 (io), 55 I/O28 (io), 56 I/O29 (io), 57 I/O30 (io), 58 I/O31 (io), 60 TMS/IN1 (in), 61 IN6 (in), 63 I/O32 (io), 64 I/O33 (io), 65 I/O34 (io), 66 I/O35 (io), 67 I/O36 (io), 68 I/O37 (io), 69 I/O38 (io), 70 I/O39 (io), 71 I/O40 (io), 72 I/O41 (io), 73 I/O42 (io), 74 I/O43 (io), 75 I/O44 (io), 76 I/O45 (io), 77 I/O46 (io), 78 I/O47 (io), 80 I/O48 (io), 81 I/O49 (io), 83 I/O50 (io), 84 I/O51 (io), 85 I/O52 (io), 86 I/O53 (io), 87 I/O54 (io), 88 I/O55 (io), 89 I/O56 (io), 90 I/O57 (io), 91 I/O58 (io), 92 I/O59 (io), 93 I/O60 (io), 94 I/O61 (io), 95 I/O62 (io), 96 I/O63 (io), 97 TCK/IN3 (in), 98 Y2 (in), 100 GOE0 (in), 103 Y1 (in), 104 IN4 (in), 105 I/O64 (io), 106 I/O65 (io), 107 I/O66 (io), 108 I/O67 (io), 109 I/O68 (io), 110 I/O69 (io), 111 I/O70 (io), 112 I/O71 (io), 113 I/O72 (io), 114 I/O73 (io), 115 I/O74 (io), 116 I/O75 (io), 117 I/O76 (io), 118 I/O77 (io), 120 I/O78 (io), 121 I/O79 (io), 123 I/O80 (io), 124 I/O81 (io), 125 I/O82 (io), 126 I/O83 (io), 127 I/O84 (io), 128 I/O85 (io), 129 I/O86 (io), 130 I/O87 (io), 131 I/O88 (io), 132 I/O89 (io), 133 I/O90 (io), 134 I/O91 (io), 135 I/O92 (io), 136 I/O93 (io), 137 I/O94 (io), 138 I/O95 (io), 140 TDO/IN2 (io), 141 IN5 (in), 143 I/O96 (io), 144 I/O97 (io), 145 I/O98 (io), 146 I/O99 (io), 147 I/O100 (io), 148 I/O101 (io), 149 I/O102 (io), 150 I/O103 (io), 151 I/O104 (io), 152 I/O105 (io), 153 I/O106 (io), 154 I/O107 (io), 155 I/O108 (io), 156 I/O109 (io), 157 I/O110 (io), 158 I/O111 (io), 160 I/O112 (io)
part B pins: 2 VCC (power), 20 VCC (power), 22 GND (power), 39 VCC (power), 42 GND (power), 59 VCC (power), 62 GND (power), 79 GND (power), 82 VCC (power), 99 GND (power), 101 VCC (power), 102 NC, 119 VCC (power), 122 GND (power), 139 GND (power), 142 VCC (power), 159 GND (power)

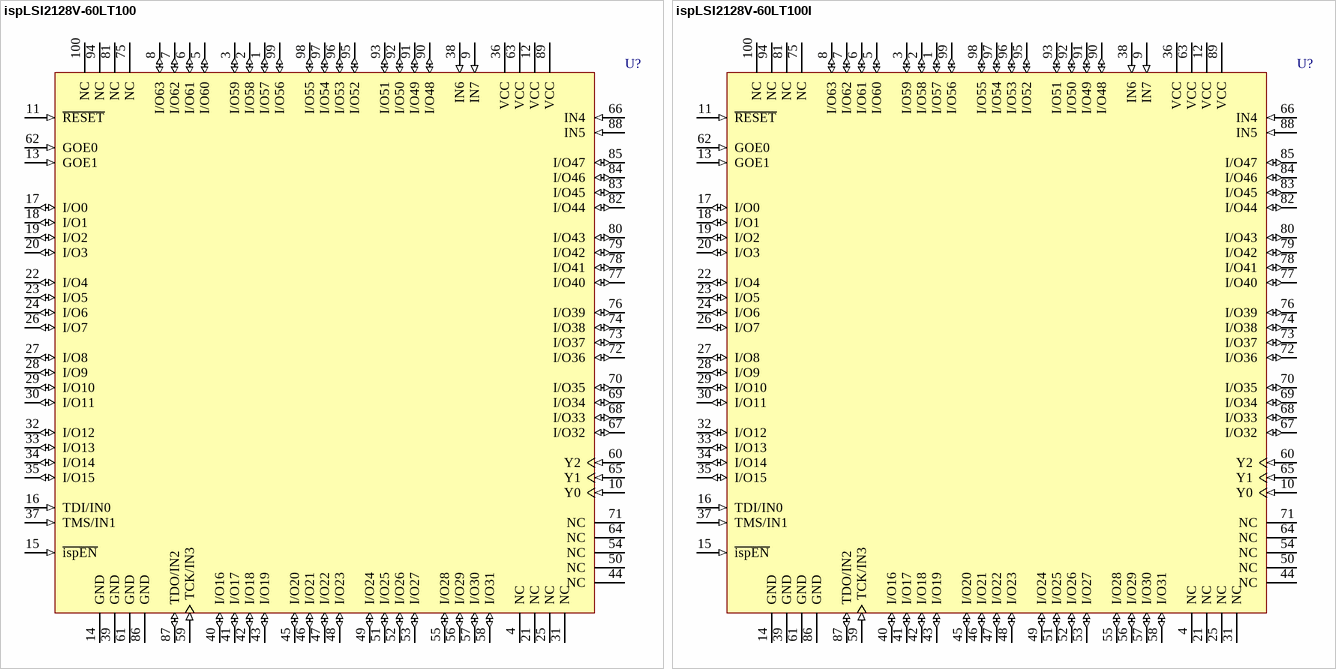
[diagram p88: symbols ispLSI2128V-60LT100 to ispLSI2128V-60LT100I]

## ispLSI2128V-60LT100
designator U?
3.3V High-Density Programmable Logic
footprint TQFP100_N (Thin QFP, 100-Leads, Body 14x14mm, Pitch 0.5mm, IPC Medium Density)
footprint TQFP100_L (Thin QFP, 100-Leads, Body 14x14mm, Pitch 0.5mm, IPC High Density)
footprint TQFP100_M (Thin QFP, 100-Leads, Body 14x14mm, Pitch 0.5mm, IPC Low Density)
3D model 2128V-TQFP100 (100-Pin Thin Quad Flat Pack (TQFP100))
pins: 1 I/O57 (io), 2 I/O58 (io), 3 I/O59 (io), 4 NC, 5 I/O60 (io), 6 I/O61 (io), 7 I/O62 (io), 8 I/O63 (io), 9 IN7 (in), 10 Y0 (in), 11 ~{RESET} (in), 12 VCC (power), 13 GOE1 (in), 14 GND (power), 15 ~{ispEN} (in), 16 TDI/IN0 (in), 17 I/O0 (io), 18 I/O1 (io), 19 I/O2 (io), 20 I/O3 (io), 21 NC, 22 I/O4 (io), 23 I/O5 (io), 24 I/O6 (io), 25 NC, 26 I/O7 (io), 27 I/O8 (io), 28 I/O9 (io), 29 I/O10 (io), 30 I/O11 (io), 31 NC, 32 I/O12 (io), 33 I/O13 (io), 34 I/O14 (io), 35 I/O15 (io), 36 VCC (power), 37 TMS/IN1 (in), 38 IN6 (in), 39 GND (power), 40 I/O16 (io), 41 I/O17 (io), 42 I/O18 (io), 43 I/O19 (io), 44 NC, 45 I/O20 (io), 46 I/O21 (io), 47 I/O22 (io), 48 I/O23 (io), 49 I/O24 (io), 50 NC, 51 I/O25 (io), 52 I/O26 (io), 53 I/O27 (io), 54 NC, 55 I/O28 (io), 56 I/O29 (io), 57 I/O30 (io), 58 I/O31 (io), 59 TCK/IN3 (in), 60 Y2 (in), 61 GND (power), 62 GOE0 (in), 63 VCC (power), 64 NC, 65 Y1 (in), 66 IN4 (in), 67 I/O32 (io), 68 I/O33 (io), 69 I/O34 (io), 70 I/O35 (io), 71 NC, 72 I/O36 (io), 73 I/O37 (io), 74 I/O38 (io), 75 NC, 76 I/O39 (io), 77 I/O40 (io), 78 I/O41 (io), 79 I/O42 (io), 80 I/O43 (io), 81 NC, 82 I/O44 (io), 83 I/O45 (io), 84 I/O46 (io), 85 I/O47 (io), 86 GND (power), 87 TDO/IN2 (io), 88 IN5 (in), 89 VCC (power), 90 I/O48 (io), 91 I/O49 (io), 92 I/O50 (io), 93 I/O51 (io), 94 NC, 95 I/O52 (io), 96 I/O53 (io), 97 I/O54 (io), 98 I/O55 (io), 99 I/O56 (io), 100 NC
